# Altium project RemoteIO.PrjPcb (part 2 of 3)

## Sheet RemoteIO_IO.SchDoc
size 431 x 279 mm; Date: Not shown in title block; ApprovedBy: Not shown in title block; CheckedBy: Not shown in title block; Author: Not shown in title block; CompanyName: Not shown in title block; Engineer: Not shown in title block; Organization: Not shown in title block; Address1: Not shown in title block; Address2: Not shown in title block; Address3: Not shown in title block; Address4: Not shown in title block; DocumentNumber: 12; Revision: Use project parameter SCH_Rev; SheetNumber: 12; SheetTotal: 14; PageSetup: Record=PageOptions¦CenterHorizontal=True¦CenterVertical=True¦PrintScale=1.00¦XCorrection=1.00¦YCorrection=1.00¦PrintKind=0¦BorderSize=5000000¦LeftOffset=0¦BottomOffset=0¦Orientation=2¦PaperLength=1000¦PaperWidth=1000¦Scale=100¦PaperSource=15¦PrintQuality=600¦MediaType=1¦DitherType=10¦PaperKind=Letter¦PrintScaleMode=1
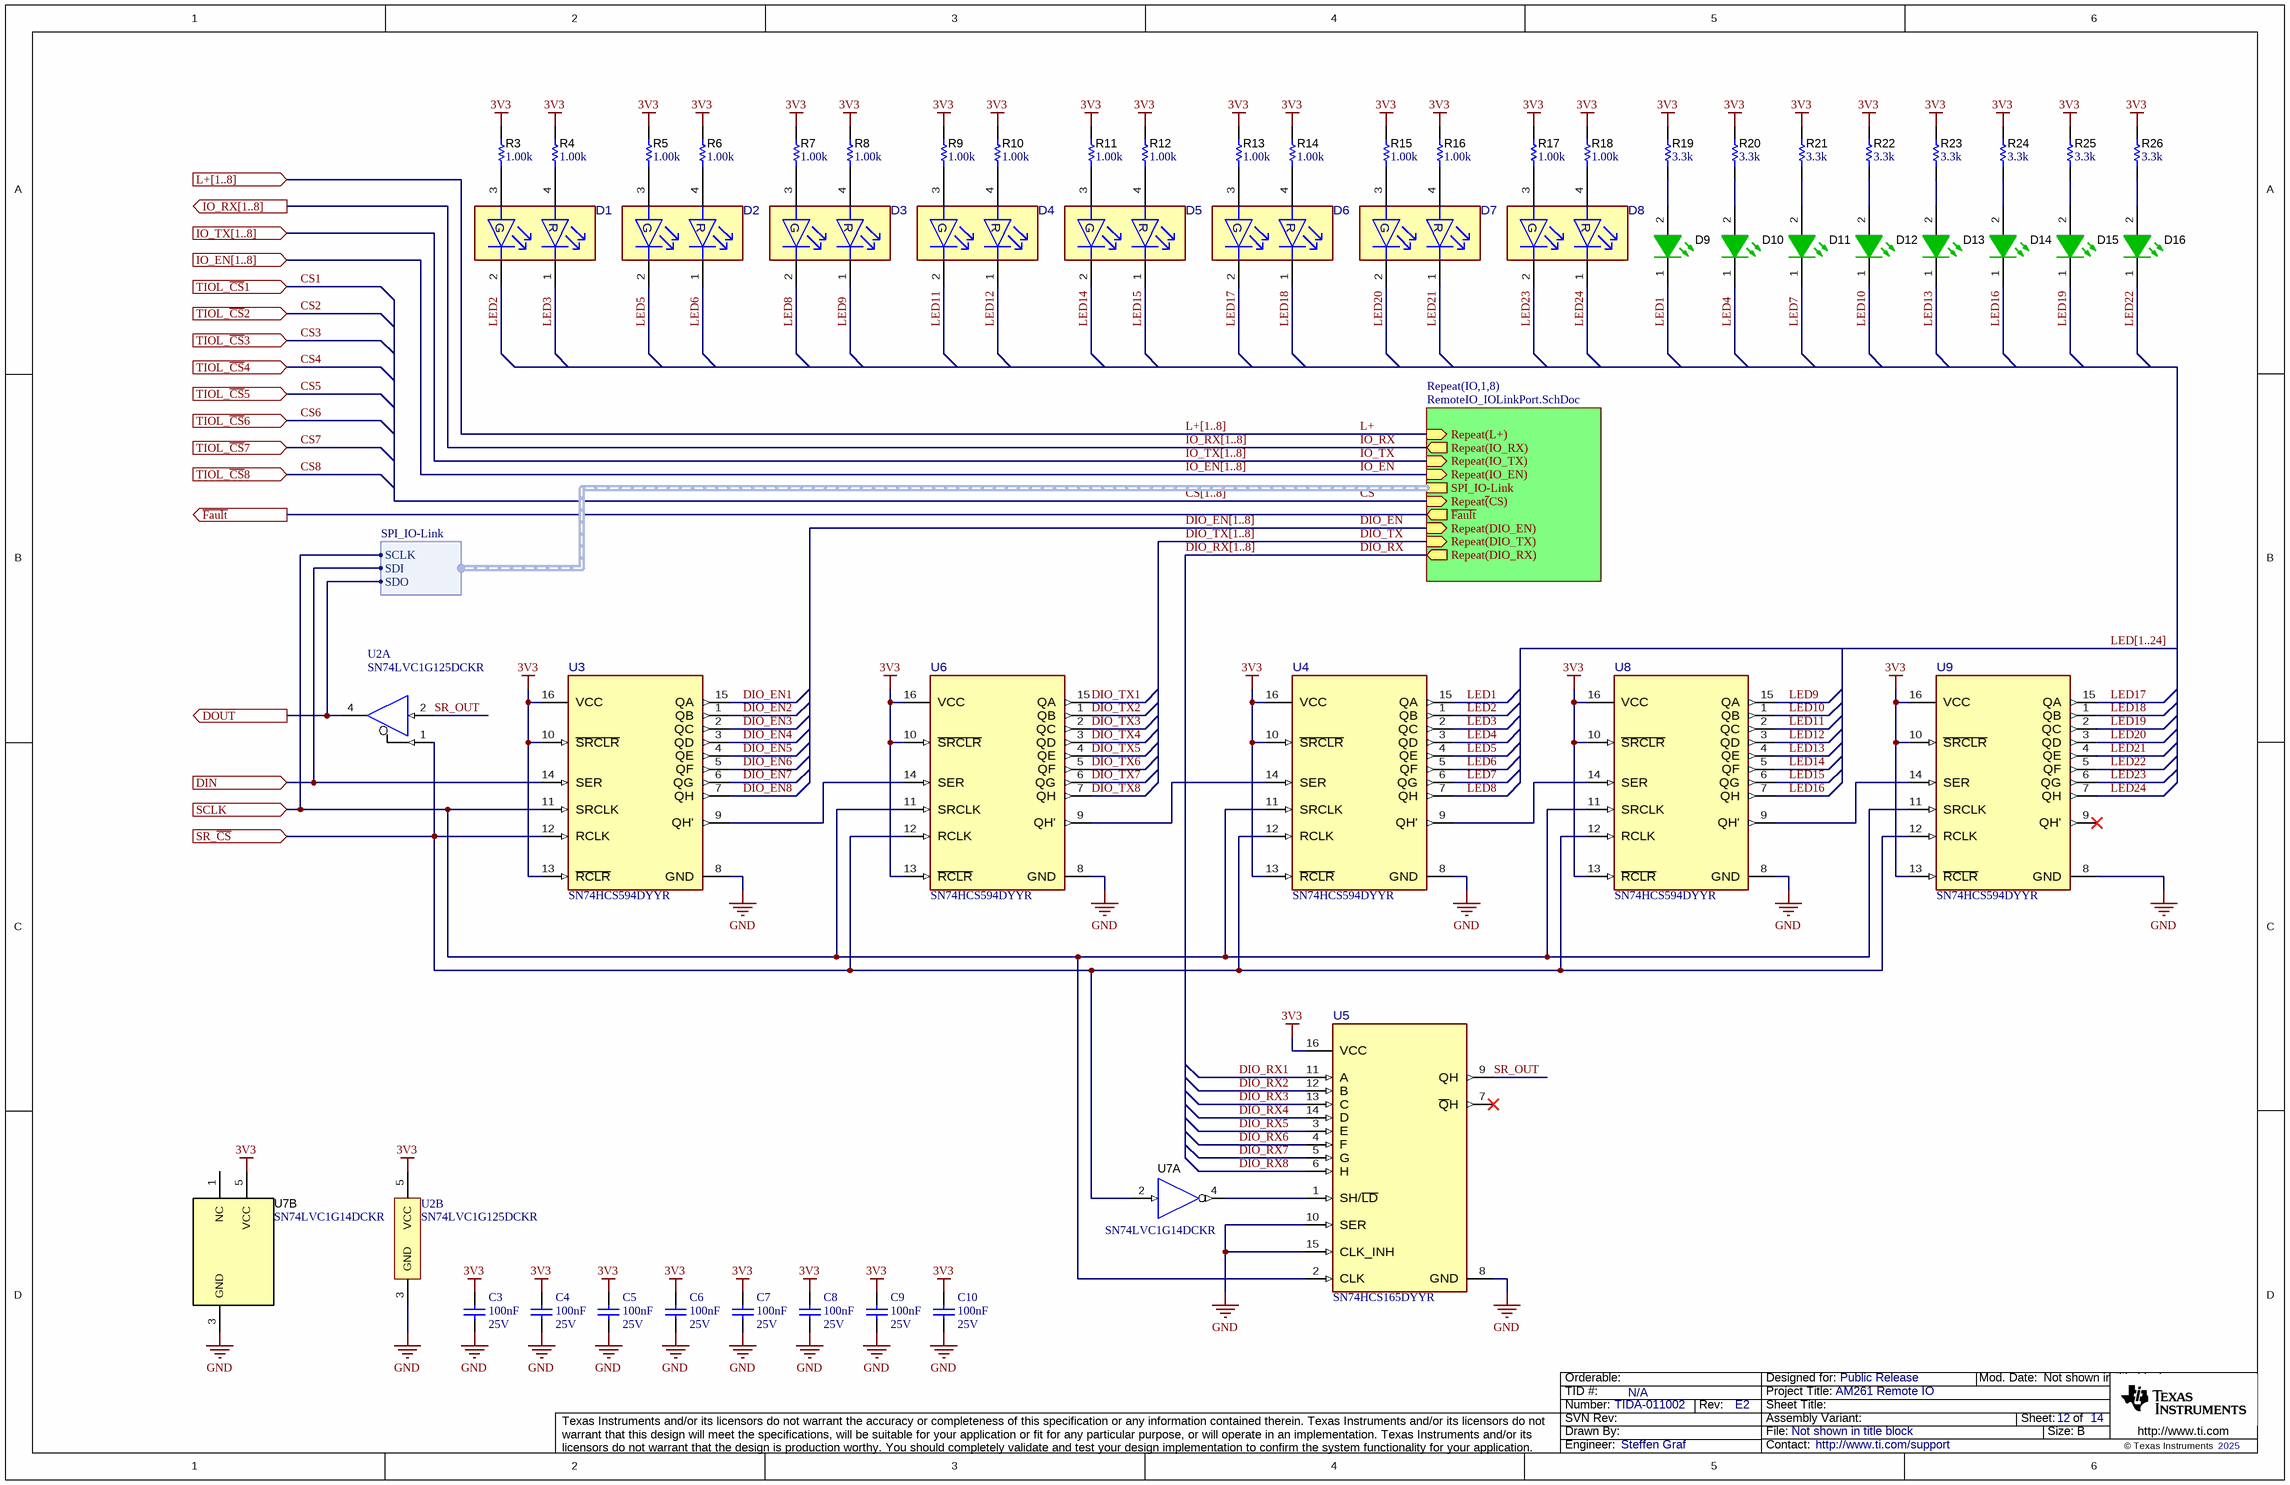
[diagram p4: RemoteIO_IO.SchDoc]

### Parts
C3  Cap_F: 100nF  Rated Voltage (DC): 25V  [WCAP-CSGP_0402_L1W0.5H0.5]  (hidden comment: 885012105018)
C4  Cap_F: 100nF  Rated Voltage (DC): 25V  [WCAP-CSGP_0402_L1W0.5H0.5]  (hidden comment: 885012105018)
C5  Cap_F: 100nF  Rated Voltage (DC): 25V  [WCAP-CSGP_0402_L1W0.5H0.5]  (hidden comment: 885012105018)
C6  Cap_F: 100nF  Rated Voltage (DC): 25V  [WCAP-CSGP_0402_L1W0.5H0.5]  (hidden comment: 885012105018)
C7  Cap_F: 100nF  Rated Voltage (DC): 25V  [WCAP-CSGP_0402_L1W0.5H0.5]  (hidden comment: 885012105018)
C8  Cap_F: 100nF  Rated Voltage (DC): 25V  [WCAP-CSGP_0402_L1W0.5H0.5]  (hidden comment: 885012105018)
C9  Cap_F: 100nF  Rated Voltage (DC): 25V  [WCAP-CSGP_0402_L1W0.5H0.5]  (hidden comment: 885012105018)
C10  Cap_F: 100nF  Rated Voltage (DC): 25V  [WCAP-CSGP_0402_L1W0.5H0.5]  (hidden comment: 885012105018)
D1  150066RG74000  [FP-150066RG74000_0606-MFG]  (value not drawn)
D2  150066RG74000  [FP-150066RG74000_0606-MFG]  (value not drawn)
D3  150066RG74000  [FP-150066RG74000_0606-MFG]  (value not drawn)
D4  150066RG74000  [FP-150066RG74000_0606-MFG]  (value not drawn)
D5  150066RG74000  [FP-150066RG74000_0606-MFG]  (value not drawn)
D6  150066RG74000  [FP-150066RG74000_0606-MFG]  (value not drawn)
D7  150066RG74000  [FP-150066RG74000_0606-MFG]  (value not drawn)
D8  150066RG74000  [FP-150066RG74000_0606-MFG]  (value not drawn)
D9  150040GS73240  [WL-SMCC_0402_Green]  (value not drawn)
D10  150040GS73240  [WL-SMCC_0402_Green]  (value not drawn)
D11  150040GS73240  [WL-SMCC_0402_Green]  (value not drawn)
D12  150040GS73240  [WL-SMCC_0402_Green]  (value not drawn)
D13  150040GS73240  [WL-SMCC_0402_Green]  (value not drawn)
D14  150040GS73240  [WL-SMCC_0402_Green]  (value not drawn)
D15  150040GS73240  [WL-SMCC_0402_Green]  (value not drawn)
D16  150040GS73240  [WL-SMCC_0402_Green]  (value not drawn)
R3  ValueDisplayed: 1.00k  [0402]  (hidden comment: CRCW04021K00FKED)
R4  ValueDisplayed: 1.00k  [0402]  (hidden comment: CRCW04021K00FKED)
R5  ValueDisplayed: 1.00k  [0402]  (hidden comment: CRCW04021K00FKED)
R6  ValueDisplayed: 1.00k  [0402]  (hidden comment: CRCW04021K00FKED)
R7  ValueDisplayed: 1.00k  [0402]  (hidden comment: CRCW04021K00FKED)
R8  ValueDisplayed: 1.00k  [0402]  (hidden comment: CRCW04021K00FKED)
R9  ValueDisplayed: 1.00k  [0402]  (hidden comment: CRCW04021K00FKED)
R10  ValueDisplayed: 1.00k  [0402]  (hidden comment: CRCW04021K00FKED)
R11  ValueDisplayed: 1.00k  [0402]  (hidden comment: CRCW04021K00FKED)
R12  ValueDisplayed: 1.00k  [0402]  (hidden comment: CRCW04021K00FKED)
R13  ValueDisplayed: 1.00k  [0402]  (hidden comment: CRCW04021K00FKED)
R14  ValueDisplayed: 1.00k  [0402]  (hidden comment: CRCW04021K00FKED)
R15  ValueDisplayed: 1.00k  [0402]  (hidden comment: CRCW04021K00FKED)
R16  ValueDisplayed: 1.00k  [0402]  (hidden comment: CRCW04021K00FKED)
R17  ValueDisplayed: 1.00k  [0402]  (hidden comment: CRCW04021K00FKED)
R18  ValueDisplayed: 1.00k  [0402]  (hidden comment: CRCW04021K00FKED)
R19  ValueDisplayed: 3.3k  [0402]  (hidden comment: CRCW04023K30JNED)
R20  ValueDisplayed: 3.3k  [0402]  (hidden comment: CRCW04023K30JNED)
R21  ValueDisplayed: 3.3k  [0402]  (hidden comment: CRCW04023K30JNED)
R22  ValueDisplayed: 3.3k  [0402]  (hidden comment: CRCW04023K30JNED)
R23  ValueDisplayed: 3.3k  [0402]  (hidden comment: CRCW04023K30JNED)
R24  ValueDisplayed: 3.3k  [0402]  (hidden comment: CRCW04023K30JNED)
R25  ValueDisplayed: 3.3k  [0402]  (hidden comment: CRCW04023K30JNED)
R26  ValueDisplayed: 3.3k  [0402]  (hidden comment: CRCW04023K30JNED)
U2  SN74LVC1G125DCKR  [DCK0005A_N]  (parts A,B of 2)
U3  SN74HCS594DYYR  [DYY0016A-MFG]
U4  SN74HCS594DYYR  [DYY0016A-MFG]
U5  SN74HCS165DYYR  [DYY0016A-MFG]
U6  SN74HCS594DYYR  [DYY0016A-MFG]
U7  SN74LVC1G14DCKR  [DCK0005A_N]  (parts A,B of 2)
U8  SN74HCS594DYYR  [DYY0016A-MFG]
U9  SN74HCS594DYYR  [DYY0016A-MFG]

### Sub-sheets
Repeat(IO,1,8) = RemoteIO_IOLinkPort.SchDoc: Repeat(L+) (in), SPI_IO-Link (harness SPI_IO-Link), Repeat(DIO_RX) (out), Repeat(DIO_EN) (in), Repeat(DIO_TX) (in), Repeat~{(}CS) (in), ~{Fault} (out), Repeat(IO_RX) (out), Repeat(IO_EN) (in), Repeat(IO_TX) (in)

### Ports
DIN (in), DOUT (out), IO_EN[1..8] (in), IO_RX[1..8] (out), IO_TX[1..8] (in), L+[1..8] (in), SCLK (in), SR_~{CS} (in), TIOL_~{CS}1 (in), TIOL_~{CS}2 (in), TIOL_~{CS}3 (in), TIOL_~{CS}4 (in), TIOL_~{CS}5 (in), TIOL_~{CS}6 (in), TIOL_~{CS}7 (in), TIOL_~{CS}8 (in), ~{Fault} (out)

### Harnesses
SPI_IO-Link: SCLK, SDI, SDO

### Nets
3V3: C3.2 C4.2 C5.2 C6.2 C7.2 C8.2 C9.2 C10.2 R3.2 R4.2 R5.2 R6.2 R7.2 R8.2 R9.2 R10.2 R11.2 R12.2 R13.2 R14.2 R15.2 R16.2 R17.2 R18.2 R19.2 R20.2 R21.2 R22.2 R23.2 R24.2 R25.2 R26.2 U2.5(VCC) U3.10(~{SRCLR}) U3.13(~{RCLR}) U3.16(VCC) U4.10(~{SRCLR}) U4.13(~{RCLR}) U4.16(VCC) U5.16(VCC) U6.10(~{SRCLR}) U6.13(~{RCLR}) U6.16(VCC) U7.5(VCC) U8.10(~{SRCLR}) U8.13(~{RCLR}) U8.16(VCC) U9.10(~{SRCLR}) U9.13(~{RCLR}) U9.16(VCC)
GND: C3.1 C4.1 C5.1 C6.1 C7.1 C8.1 C9.1 C10.1 U2.3(GND) U3.8(GND) U4.8(GND) U5.8(GND) U5.10(SER) U5.15(CLK_INH) U6.8(GND) U7.3(GND) U8.8(GND) U9.8(GND)
~{Fault}: port ~{Fault}, sheet Repeat(IO,1,8)/~{Fault}
DIN: U3.14(SER) ; port DIN, sheet Repeat(IO,1,8)/SPI_IO-Link.SDI
DIO_EN1: U3.15(QA)
DIO_EN2: U3.1(QB)
DIO_EN3: U3.2(QC)
DIO_EN4: U3.3(QD)
DIO_EN5: U3.4(QE)
DIO_EN6: U3.5(QF)
DIO_EN7: U3.6(QG)
DIO_EN8: U3.7(QH)
DIO_RX1: U5.11(A)
DIO_RX2: U5.12(B)
DIO_RX3: U5.13(C)
DIO_RX4: U5.14(D)
DIO_RX5: U5.3(E)
DIO_RX6: U5.4(F)
DIO_RX7: U5.5(G)
DIO_RX8: U5.6(H)
DIO_TX1: U6.15(QA)
DIO_TX2: U6.1(QB)
DIO_TX3: U6.2(QC)
DIO_TX4: U6.3(QD)
DIO_TX5: U6.4(QE)
DIO_TX6: U6.5(QF)
DIO_TX7: U6.6(QG)
DIO_TX8: U6.7(QH)
DOUT: U2.4(Y) ; port DOUT, sheet Repeat(IO,1,8)/SPI_IO-Link.SDO
LED1: D9.1(K) U4.15(QA)
LED2: D1.2(G_Cathode) U4.1(QB)
LED3: D1.1(R_Cathode) U4.2(QC)
LED4: D10.1(K) U4.3(QD)
LED5: D2.2(G_Cathode) U4.4(QE)
LED6: D2.1(R_Cathode) U4.5(QF)
LED7: D11.1(K) U4.6(QG)
LED8: D3.2(G_Cathode) U4.7(QH)
LED9: D3.1(R_Cathode) U8.15(QA)
LED10: D12.1(K) U8.1(QB)
LED11: D4.2(G_Cathode) U8.2(QC)
LED12: D4.1(R_Cathode) U8.3(QD)
LED13: D13.1(K) U8.4(QE)
LED14: D5.2(G_Cathode) U8.5(QF)
LED15: D5.1(R_Cathode) U8.6(QG)
LED16: D14.1(K) U8.7(QH)
LED17: D6.2(G_Cathode) U9.15(QA)
LED18: D6.1(R_Cathode) U9.1(QB)
LED19: D15.1(K) U9.2(QC)
LED20: D7.2(G_Cathode) U9.3(QD)
LED21: D7.1(R_Cathode) U9.4(QE)
LED22: D16.1(K) U9.5(QF)
LED23: D8.2(G_Cathode) U9.6(QG)
LED24: D8.1(R_Cathode) U9.7(QH)
SCLK: U3.11(SRCLK) U4.11(SRCLK) U5.2(CLK) U6.11(SRCLK) U8.11(SRCLK) U9.11(SRCLK) ; port SCLK, sheet Repeat(IO,1,8)/SPI_IO-Link.SCLK
SR_~{CS}: U2.1(~{OE}) U3.12(RCLK) U4.12(RCLK) U6.12(RCLK) U7.2(A) U8.12(RCLK) U9.12(RCLK) ; port SR_~{CS}
SR_OUT: U2.2(A) U5.9(QH)
NetD1_3: D1.3(G_Anode) R3.1
NetD1_4: D1.4(R_Anode) R4.1
NetD2_3: D2.3(G_Anode) R5.1
NetD2_4: D2.4(R_Anode) R6.1
NetD3_3: D3.3(G_Anode) R7.1
NetD3_4: D3.4(R_Anode) R8.1
NetD4_3: D4.3(G_Anode) R9.1
NetD4_4: D4.4(R_Anode) R10.1
NetD5_3: D5.3(G_Anode) R11.1
NetD5_4: D5.4(R_Anode) R12.1
NetD6_3: D6.3(G_Anode) R13.1
NetD6_4: D6.4(R_Anode) R14.1
NetD7_3: D7.3(G_Anode) R15.1
NetD7_4: D7.4(R_Anode) R16.1
NetD8_3: D8.3(G_Anode) R17.1
NetD8_4: D8.4(R_Anode) R18.1
NetD9_2: D9.2(A) R19.1
NetD10_2: D10.2(A) R20.1
NetD11_2: D11.2(A) R21.1
NetD12_2: D12.2(A) R22.1
NetD13_2: D13.2(A) R23.1
NetD14_2: D14.2(A) R24.1
NetD15_2: D15.2(A) R25.1
NetD16_2: D16.2(A) R26.1
NetU3_9: U3.9(QH') U6.14(SER)
NetU4_9: U4.9(QH') U8.14(SER)
NetU4_14: U4.14(SER) U6.9(QH')
NetU5_1: U5.1(SH/~{LD}) U7.4(Y)
NetU8_9: U8.9(QH') U9.14(SER)

Not connected (* = marked no-connect by the designer): U5 7(~{Q}H)*; U7 1(NC); U9 9(QH')*

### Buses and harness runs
bus CS[1..8]
bus DIO_EN[1..8]
bus DIO_RX[1..8]
bus DIO_TX[1..8]
bus IO_EN[1..8] = port IO_EN[1..8]
bus IO_RX[1..8] = port IO_RX[1..8]
bus IO_TX[1..8] = port IO_TX[1..8]
bus L+[1..8] = port L+[1..8]
bus LED[1..24]

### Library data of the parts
C3-C10 = CMP-0119143-1: WCAP-CSGP Multilayer Ceramic Chip Capacitor, General Purpose, size 0402, X5R, 100nF, 25VDC; Manufacturer: Wurth Elektronik; PartNumber: '885012105018; Capacitance Tolerance: +/-20%; Case/Size Code: 0402; Dissipation Factor: 10%; Insulation Resistance: 5GOhm; Technical Reference: X5R0402104M025DFCT10000
D1-D8 = CMP-0125609-1: Green, Red 520nm Green, 625nm Red LED Indication - Discrete 3.2V Green, 2V Red 0606 (1616 Metric); Manufacturer: Wurth; Angle: 130°; Color: Red, Green; LambdaD: 625/520nm; LambdaP: 630/515nm; SizeZ_mm: 0.8mm; Tjmax_C: 95°C; Vr_V: 5V; AEC Qualified: No; Forward Current: 20mA; Led Orientation: Top View; Luminous Intensity: 300/560mcd; Value: Red/Green
D9-D16 = CMP-0081765-2: LED, Green, SMD; Manufacturer: Wurth Elektronik; Vr_V: 5V; Io_A: 20mA; Tjmax_C: 95°C; Ir_A: 10µA; Power_TotalModule: 99mW; Value2: 3.2V; SizeArea_mm2: 0.5; SizeX_mm: 1; Value1: 0.099W; Angle: 120; Type: InGaN; SizeAreaWB_mm2: 3
R3-R18 = CMP-0026071-3: RES, 1.00 k, 1%, 0.063 W, AEC-Q200 Grade 0, 0402; Manufacturer: Vishay-Dale; Power_W: 63mW; TempCo: 100 ppm/C; Value_Code: 1k00; Value: 1.00k; EIA_Code: E96; Res_ohm: 1k; SizeX_mm: 1; SizeY_mm: 0.5; SizeZ_mm: 0.6; Value2: 0.063W; AEC Qualified: Y; VDC_V: 50V; AEC Category: Q200; AEC Grade: 0
R19-R26 = CMP-0026918-5: RES, 3.3 k, 5%, 0.063 W, AEC-Q200 Grade 0, 0402; Manufacturer: Vishay-Dale; Power_W: 63mW; TempCo: 200 ppm/C; Value_Code: 3k30; Value: 3.3k; EIA_Code: E24; SizeX_mm: 1; SizeY_mm: 0.5; SizeZ_mm: 0.6; Value2: 0.063W; AEC Qualified: Y; VDC_V: 50V; AEC Category: Q200; AEC Grade: 0
U2 = CMP-0051326-3: Single Bus Buffer Gate With 3-State Outputs, DCK0005A, LARGE T&R; Manufacturer: Texas Instruments; Bits(#): 1; tpd @ Nom Voltage(Max)(ns): 9,5.5,4.5,4; 3-State Output: Yes; Output Type: CMOS; Sub-Family: Non-Inverting Buffer/Driver; Logic: True; Output Drive (IOL/IOH)(Max)(mA): 32/-32; Voltage(Nom)(V): 1.8,2.5,3.3,5; ICC @ Nom Voltage(Max)(mA): 0.01; Technology Family: LVC; VCC(Min)(V): 1.65; VCC(Max)(V): 5.5; F @ Nom Voltage(Max)(Mhz): 150; Rating: Catalog; Input Type: CMOS/TTL; Schmitt Trigger: No; AEC Category: Q200; AEC Qualified: N; CompType: IC; SizeAreaWB_mm2: 9.3; SizeArea_mm2: 4.2; SizeX_mm: 2.1; SizeY_mm: 2.0; SizeZ_mm: 1.1
U3 U4 U6 U8 U9 = CMP-0093041-1: Eight-bit shift registers with Schmitt-trigger inputs and with output registers; Manufacturer: Texas Instruments; Number Of Inputs: 5; Max Supply Voltage: 6V; Min Supply Voltage: 2V; Propagation Delay: 19ns; Frequency_Fixed: 115MHz; AEC Qualified: No; Standoff Height: 0mm; TJmax_C: +150°C; TaMin_C: -40°C; PositionCount: 1; Nominal Supply Current: 0.1uA; SizeZ_mm: 1.1mm; TaMax_C: +125°C; Number Of Outputs: 8
U5 = CMP-0093040-1: Counter Shift Registers 8-bit parallel-load shift registers with Schmitt-trigger inputs; Manufacturer: Texas Instruments; TaMin_C: -40°C; SizeZ_mm: 1.1mm; PositionCount: 1; TaMax_C: +125°C; Number Of Inputs: 8; Frequency_Fixed: 170MHz; Propagation Delay: 39ns; Max Supply Voltage: 6V; Min Supply Voltage: 2V; AEC Qualified: No; TJmax_C: +150°C; Standoff Height: 0mm; Nominal Supply Current: 0.1uA
U7 = CMP-0051641-4: Single Schmitt-Trigger Inverter, DCK0005A (SOT-SC70-5); Manufacturer: Texas Instruments; Alternate PartNumber: SN74LVC1G14DCKT; Output Drive (IOL/IOH)(Max)(mA): 32/-32; Schmitt Trigger: Yes; Logic: Inverting; Bits(#): 1; Rating: Catalog; tpd @ Nom Voltage(Max)(ns): 11,6.5,5.5,5; Voltage(Nom)(V): 1.8,2.5,3.3,5; Output Type: CMOS; VCC(Min)(V): 1.65; ICC @ Nom Voltage(Max)(mA): 0.01; Input Type: CMOS/TTL; F @ Nom Voltage(Max)(Mhz): 150; VCC(Max)(V): 5.5; 3-State Output: No; AEC Category: Q200; AEC Qualified: N; CompType: IC; Green_Lifecycle: Active; Green_REACh: Passed; SizeAreaWB_mm2: 9.3; SizeArea_mm2: 4.2; SizeX_mm: 2.1; SizeY_mm: 2.0; SizeZ_mm: 1.1

## Sheet RemoteIO_IOLinkPort.SchDoc
size 431 x 279 mm; Date: Not shown in title block; ApprovedBy: Not shown in title block; CheckedBy: Not shown in title block; Author: Not shown in title block; CompanyName: Not shown in title block; Engineer: Not shown in title block; Organization: Not shown in title block; Address1: Not shown in title block; Address2: Not shown in title block; Address3: Not shown in title block; Address4: Not shown in title block; DocumentNumber: 3; Revision: Use project parameter SCH_Rev; SheetNumber: 3; SheetTotal: 14; PageSetup: Record=PageOptions¦CenterHorizontal=True¦CenterVertical=True¦PrintScale=1.00¦XCorrection=1.00¦YCorrection=1.00¦PrintKind=0¦BorderSize=5000000¦LeftOffset=0¦BottomOffset=0¦Orientation=2¦PaperLength=1000¦PaperWidth=1000¦Scale=100¦PaperSource=15¦PrintQuality=600¦MediaType=1¦DitherType=10¦PaperKind=Letter¦PrintScaleMode=1
Used 8 times, as channels IOs/IO1, IOs/IO2, IOs/IO3, IOs/IO4, IOs/IO5, IOs/IO6, IOs/IO7, IOs/IO8. Parts and nets are listed once, with the designators drawn on the sheet.
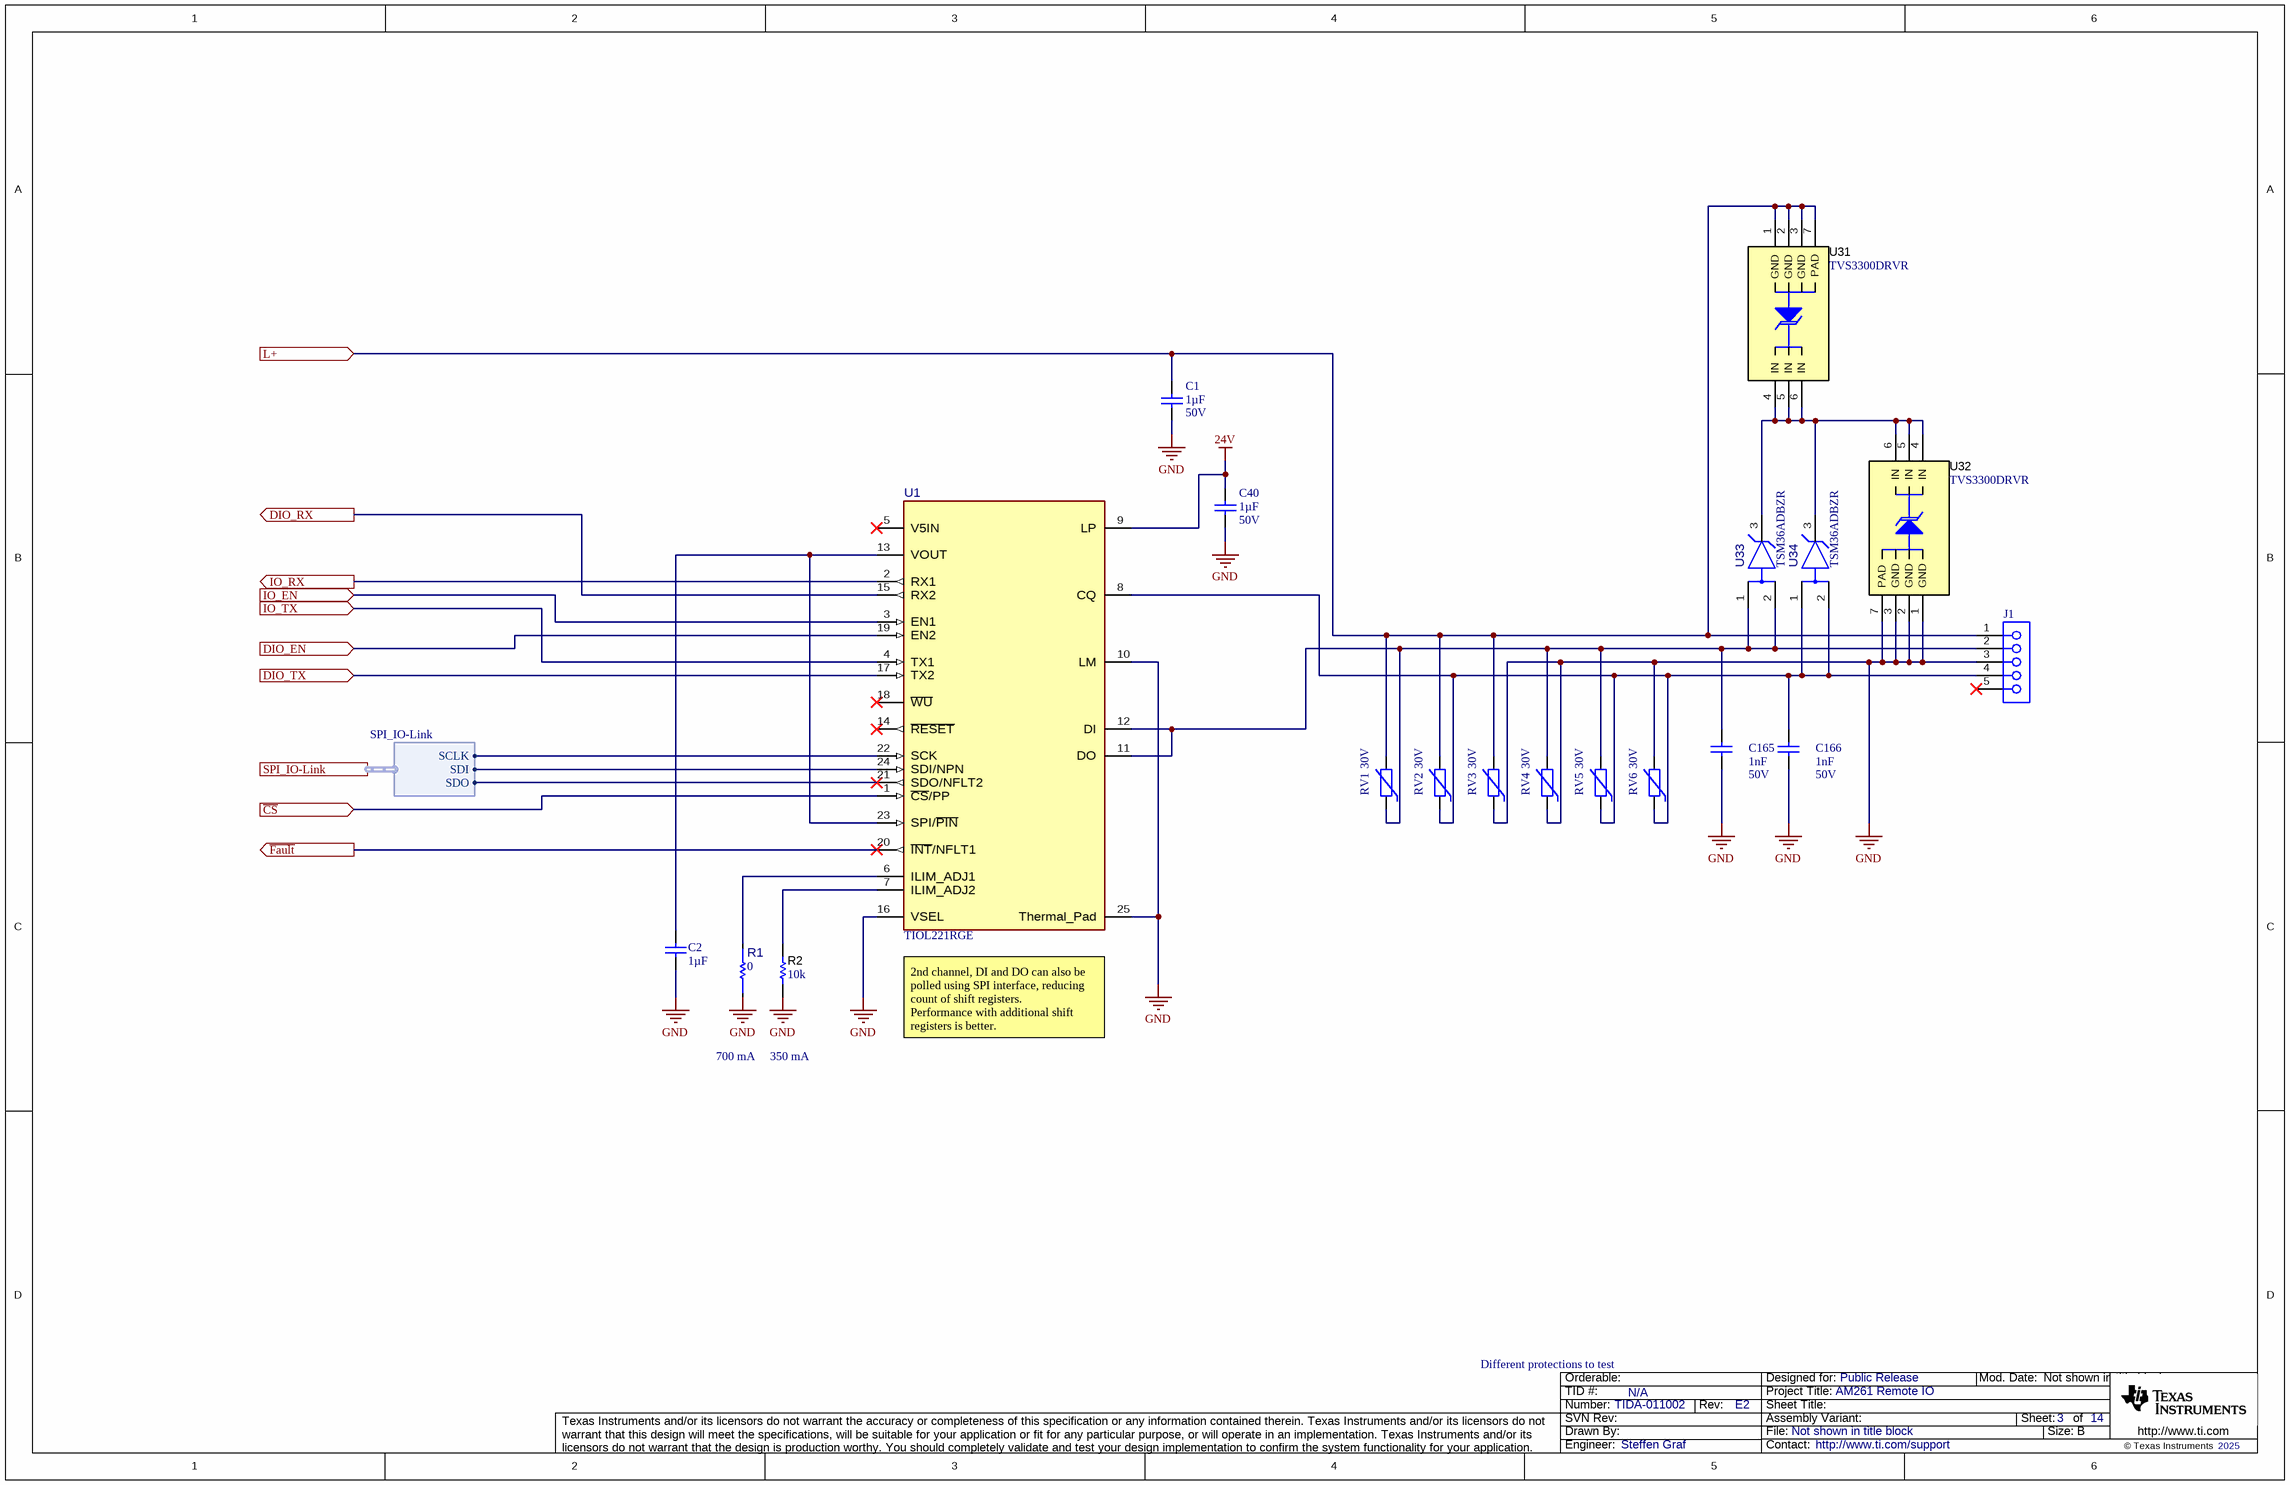
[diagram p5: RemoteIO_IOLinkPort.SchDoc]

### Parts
C1  Cap_F: 1µF  Rated Voltage (DC): 50V  [WCAP-CSGP_1206_L3.2W1.6H1.6]  (hidden comment: 885012208093)
C2  Cap_F: 1µF  [WCAP-CSGP_0603_L1.6W0.8H0.8_Reflow]  (hidden comment: 885012206052)
C40  Cap_F: 1µF  Rated Voltage (DC): 50V  [WCAP-CSGP_1206_L3.2W1.6H1.6]  (hidden comment: 885012208093)
C165  Cap_F: 1nF  Rated Voltage (DC): 50V  [WCAP-CSGP_0603_L1.6W0.8H0.8_Reflow]  (hidden comment: 885012006063)
C166  Cap_F: 1nF  Rated Voltage (DC): 50V  [WCAP-CSGP_0603_L1.6W0.8H0.8_Reflow]  (hidden comment: 885012006063)
J1  643260100605  [643260100605]  (value not drawn)
R1  value 0  [FP-CRCW04020000Z0EDC_0402-IPC_A]  (hidden comment: CRCW04020000Z0EDC)
R2  ValueDisplayed: 10k  [0402]  (hidden comment: CRCW040210K0JNED)
RV1  Operating Voltage (AC): 30V  [WE-VS_0603]  (hidden comment: 30VAC, 38VDC)
RV2  Operating Voltage (AC): 30V  [WE-VS_0603]  (hidden comment: 30VAC, 38VDC)
RV3  Operating Voltage (AC): 30V  [WE-VS_0603]  (hidden comment: 30VAC, 38VDC)
RV4  Operating Voltage (AC): 30V  [WE-VS_0603]  (hidden comment: 30VAC, 38VDC)
RV5  Operating Voltage (AC): 30V  [WE-VS_0603]  (hidden comment: 30VAC, 38VDC)
RV6  Operating Voltage (AC): 30V  [WE-VS_0603]  (hidden comment: 30VAC, 38VDC)
U1  TIOL221RGE  [RGE0024H-MFG]
U31  TVS3300DRVR  [DRV0006A]
U32  TVS3300DRVR  [DRV0006A]
U33  TSM36ADBZR  [DBZ0003A-MFG]
U34  TSM36ADBZR  [DBZ0003A-MFG]

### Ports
DIO_EN (in), DIO_RX (out), DIO_TX (in), IO_EN (in), IO_RX (out), IO_TX (in), L+ (in), SPI_IO-Link (harness SPI_IO-Link), ~{CS} (in), ~{Fault} (out)

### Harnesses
SPI_IO-Link: SCLK, SDI, SDO

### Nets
24V: C40.2 U1.9(LP)
GND: C1.1 C2.1 C40.1 C165.1 C166.1 J1.3 R1.1 R2.1 RV3.1 RV4.1 RV6.2 U1.10(LM) U1.16(VSEL) U1.25(Thermal_Pad) U32.1(GND) U32.2(GND) U32.3(GND) U32.7(PAD)
~{CS}: U1.1(~{CS}/PP) ; port ~{CS}
~{Fault}: U1.20(~{INT}/NFLT1) ; port ~{Fault}
DIO_EN: U1.19(EN2) ; port DIO_EN
DIO_RX: U1.15(RX2) ; port DIO_RX
DIO_TX: U1.17(TX2) ; port DIO_TX
IO_EN: U1.3(EN1) ; port IO_EN
IO_RX: U1.2(RX1) ; port IO_RX
IO_TX: U1.4(TX1) ; port IO_TX
L+: C1.2 J1.1 RV1.2 RV2.2 RV3.2 U31.1(GND) U31.2(GND) U31.3(GND) U31.7(PAD) ; port L+
NetC2_2: C2.2 U1.13(VOUT) U1.23(SPI/~{PIN})
NetC165_2: C165.2 J1.2 RV1.1 RV4.2 RV5.2 U1.11(DO) U1.12(DI) U33.1(GND) U33.2(GND)
NetC166_2: C166.2 J1.4 RV2.1 RV5.1 RV6.1 U1.8(CQ) U34.1(GND) U34.2(GND)
NetR1_2: R1.2 U1.6(ILIM_ADJ1)
NetR2_2: R2.2 U1.7(ILIM_ADJ2)
NetU1_21: U1.21(SDO/NFLT2) ; port SPI_IO-Link.SDO
NetU1_22: U1.22(SCK) ; port SPI_IO-Link.SCLK
NetU1_24: U1.24(SDI/NPN) ; port SPI_IO-Link.SDI
NetU31_4: U31.4(IN) U31.5(IN) U31.6(IN) U32.4(IN) U32.5(IN) U32.6(IN) U33.3(IO) U34.3(IO)

Not connected (* = marked no-connect by the designer): J1 5*; U1 5(V5IN)* 14(~{RESET})* 18(~{WU})*

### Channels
IOs/IO1: designators end in .1; ports DIO_EN=DIO_EN1 DIO_RX=DIO_RX1 DIO_TX=DIO_TX1 IO_EN=IO_EN1 IO_RX=IO_RX1 IO_TX=IO_TX1 L+=L+1 ~{CS}=CS1 ~{Fault}=~{Fault}
IOs/IO2: designators end in .2; ports DIO_EN=DIO_EN2 DIO_RX=DIO_RX2 DIO_TX=DIO_TX2 IO_EN=IO_EN2 IO_RX=IO_RX2 IO_TX=IO_TX2 L+=L+2 ~{CS}=CS2 ~{Fault}=~{Fault}
IOs/IO3: designators end in .3; ports DIO_EN=DIO_EN3 DIO_RX=DIO_RX3 DIO_TX=DIO_TX3 IO_EN=IO_EN3 IO_RX=IO_RX3 IO_TX=IO_TX3 L+=L+3 ~{CS}=CS3 ~{Fault}=~{Fault}
IOs/IO4: designators end in .4; ports DIO_EN=DIO_EN4 DIO_RX=DIO_RX4 DIO_TX=DIO_TX4 IO_EN=IO_EN4 IO_RX=IO_RX4 IO_TX=IO_TX4 L+=L+4 ~{CS}=CS4 ~{Fault}=~{Fault}
IOs/IO5: designators end in .5; ports DIO_EN=DIO_EN5 DIO_RX=DIO_RX5 DIO_TX=DIO_TX5 IO_EN=IO_EN5 IO_RX=IO_RX5 IO_TX=IO_TX5 L+=L+5 ~{CS}=CS5 ~{Fault}=~{Fault}
IOs/IO6: designators end in .6; ports DIO_EN=DIO_EN6 DIO_RX=DIO_RX6 DIO_TX=DIO_TX6 IO_EN=IO_EN6 IO_RX=IO_RX6 IO_TX=IO_TX6 L+=L+6 ~{CS}=CS6 ~{Fault}=~{Fault}
IOs/IO7: designators end in .7; ports DIO_EN=DIO_EN7 DIO_RX=DIO_RX7 DIO_TX=DIO_TX7 IO_EN=IO_EN7 IO_RX=IO_RX7 IO_TX=IO_TX7 L+=L+7 ~{CS}=CS7 ~{Fault}=~{Fault}
IOs/IO8: designators end in .8; ports DIO_EN=DIO_EN8 DIO_RX=DIO_RX8 DIO_TX=DIO_TX8 IO_EN=IO_EN8 IO_RX=IO_RX8 IO_TX=IO_TX8 L+=L+8 ~{CS}=CS8 ~{Fault}=~{Fault}

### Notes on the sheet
- (near U1) 2nd channel, DI and DO can also be polled using SPI interface, reducing count of shift registers.
  Performance with additional shift registers is better.
- 700 mA
- 350 mA
- Different protections to test

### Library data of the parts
C1 C40 = CMP-0119636-1: WCAP-CSGP Multilayer Ceramic Chip Capacitor, General Purpose, size 1206, X7R, 1µF, 50VDC; Manufacturer: Wurth Elektronik; PartNumber: '885012208093; Capacitance Tolerance: +/-10%; Case/Size Code: 1206; Dissipation Factor: 3%; Insulation Resistance: 0.5GOhm; Technical Reference: X7R1206105K050DFCT10000
C2 = CMP-0115435-1: WCAP-CSGP Multilayer Ceramic Chip Capacitor, General Purpose, size 0603, X7R, 1µF, 16VDC; Manufacturer: Wurth Elektronik; Capacitance Tolerance: +/-10%; Case/Size Code: 0603; Dissipation Factor: 10%; Insulation Resistance: 0.1GOhm; Rated Voltage (DC): 16V; Technical Reference: X7R0603105K016DFCT10000
C165 C166 = CMP-0118895-1: WCAP-CSGP Multilayer Ceramic Chip Capacitor, General Purpose, size 0603, NP0, 1nF, 50VDC; Manufacturer: Wurth Elektronik; Capacitance Tolerance: +/-5%; Case/Size Code: 0603; Insulation Resistance: 10GOhm; Q Factor: 1000; Technical Reference: NP00603102J050DFCT10000
J1 = 643260100605: WR-CIRCM12 Screw Mating Panel Connector Female Metal PG9, THT, 5p; Manufacturer: Wurth Elektronik; PartNumber: '643260100605; Insulation Resistance: 100MΩ; Polarity: 5; Rated Current: 5A; Working Voltage: 60V; Withstanding Voltage: 1000V AC
R1 = CMP-0093210-1: Jumper 0.063W, 1/16W Chip Resistor 0402 (1005 Metric) - Thick Film; Manufacturer: Vishay; AEC Qualified: No; VDC_V: 50V; Power_W: 63mW; SizeZ_mm: 0.35mm
R2 = CMP-0026825-5: RES, 10 k, 5%, 0.063 W, AEC-Q200 Grade 0, 0402; Manufacturer: Vishay-Dale; Power_W: 63mW; TempCo: 200 ppm/C; Value_Code: 10k0; Value: 10k; EIA_Code: E24; SizeX_mm: 1; SizeY_mm: 0.5; SizeZ_mm: 0.6; Value2: 0.063W; AEC Qualified: Y; VDC_V: 50V; AEC Category: Q200; AEC Grade: 0
RV1-RV6 = 82556300: WE-VS SMT Varistor, size 0603, 30VAC, 38VDC; Manufacturer: Wurth Elektronik; Case/Size Code: 0603; Clamping Voltage: 77V; Energy Absorption: 0.1J; Operating Voltage (DC): 38V; (Reverse) Breakdown Voltage: 47V; (Reverse) Peak Pulse Current: 30A; Value: 30V
U1 = CMP-0044977-1: Dual Channel IO-Link Device PHY with Integrated LDO and SPI Interface; Manufacturer: Texas Instruments; SizeZ_mm: 1mm; AEC Qualified: No; Interface: SPI,Other; Max Supply Voltage: 36V; Min Supply Voltage: 4.5V; Standoff Height: 0mm; TaMax_C: +125°C; TaMin_C: -40°C; TJmax_C: +150°C
U31 U32 = CMP-0013424-7: 33-V Precision Surge Protection Clamp, DRV0006A (WSON-6); Manufacturer: Texas Instruments; Alternate PartNumber: TVS3300DRVT; SizeX_mm: 2; CompType: IC; SizeZ_mm: 0.8; SizeArea_mm2: 4; SizeAreaWB_mm2: 9; U/M: EA
U33 U34 = CMP-0097428-1: Surge Protection Device in SOT-23 Package; Manufacturer: Texas Instruments; Breakdown Voltage: 37.8V; TJmax_C: +150°C; Number Of Channels: 1; Direction: Unidirectional; Standoff Height: 0.01mm; Cap_F: 50pF; VRWM: 36V; Ipp: 41A; Ppk: 2000W; SizeZ_mm: 1.12mm; TaMin_C: -55°C; AEC Qualified: No; Clamping Voltage: 57V

## Sheet RemoteIO_Hardware.SchDoc
size 431 x 279 mm; Date: Not shown in title block; ApprovedBy: Not shown in title block; CheckedBy: Not shown in title block; Author: Not shown in title block; CompanyName: Not shown in title block; Engineer: Not shown in title block; Organization: Not shown in title block; Address1: Not shown in title block; Address2: Not shown in title block; Address3: Not shown in title block; Address4: Not shown in title block; DocumentNumber: 14; Revision: Use project parameter SCH_Rev; SheetNumber: 14; SheetTotal: 14; PageSetup: Record=PageOptions¦CenterHorizontal=True¦CenterVertical=True¦PrintScale=1.00¦XCorrection=1.00¦YCorrection=1.00¦PrintKind=0¦BorderSize=5000000¦LeftOffset=0¦BottomOffset=0¦Orientation=2¦PaperLength=1000¦PaperWidth=1000¦Scale=100¦PaperSource=15¦PrintQuality=600¦MediaType=1¦DitherType=10¦PaperKind=Letter¦PrintScaleMode=1
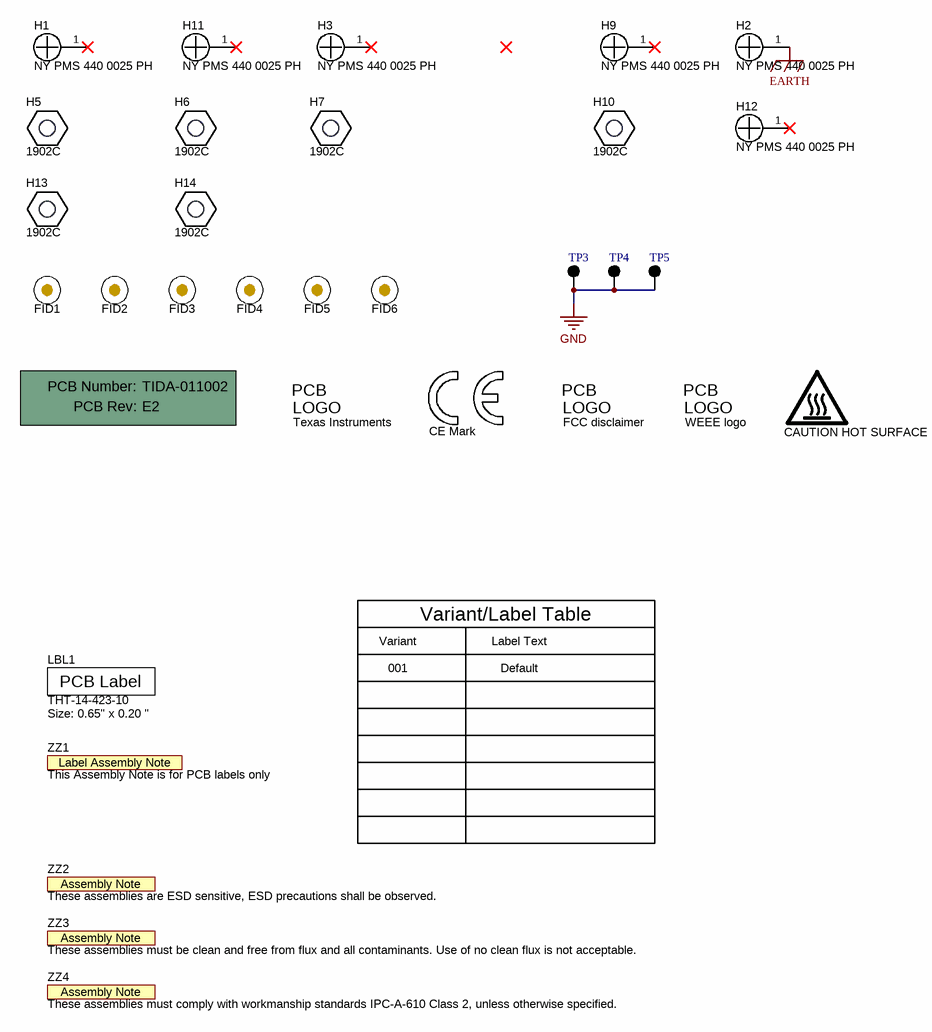
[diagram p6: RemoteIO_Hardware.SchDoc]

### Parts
!PCB  Printed Circuit Board  (value not drawn)  (mechanical)
FID1  Fiducial  [Fiducial10-20]  (value not drawn)
FID2  Fiducial  [Fiducial10-20]  (value not drawn)
FID3  Fiducial  [Fiducial10-20]  (value not drawn)
FID4  Fiducial  [Fiducial10-20]  (value not drawn)
FID5  Fiducial  [Fiducial10-20]  (value not drawn)
FID6  Fiducial  [Fiducial10-20]  (value not drawn)
H1  NY PMS 440 0025 PH  [NY PMS 440 0025 PH]
H2  NY PMS 440 0025 PH  [NY PMS 440 0025 PH]
H3  NY PMS 440 0025 PH  [NY PMS 440 0025 PH]
H5  1902C  [Keystone_1902C]
H6  1902C  [Keystone_1902C]
H7  1902C  [Keystone_1902C]
H9  NY PMS 440 0025 PH  [NY PMS 440 0025 PH]
H10  1902C  [Keystone_1902C]
H11  NY PMS 440 0025 PH  [NY PMS 440 0025 PH]
H12  NY PMS 440 0025 PH  [NY PMS 440 0025 PH]
H13  1902C  [Keystone_1902C]
H14  1902C  [Keystone_1902C]
LBL1  THT-14-423-10  Note: Size: 0.65" x 0.20 "  [Label_650x200]
Logo1  Texas Instruments  [TI_Stacked_Overlay_Small]  (no BOM)
Logo2  CE Mark  [CE_Mark_5mm]  (no BOM)
Logo3  FCC disclaimer  [FCC_disclaimer]  (no BOM)
Logo4  WEEE logo  [WEEE_Minimum]  (no BOM)
Logo5  CAUTION HOT SURFACE  [IEC_HotSurface_Small]  (no BOM)
TP3  5006  [Keystone5006]  (value not drawn)
TP4  5006  [Keystone5006]  (value not drawn)
TP5  5006  [Keystone5006]  (value not drawn)
ZZ1  This Assembly Note is for PCB labels only  [AssemblyNoteLabel]  (no BOM)
ZZ2  These assemblies are ESD sensitive, ESD precautions shall be observed.  [AssemblyNote]  (no BOM)
ZZ3  These assemblies must be clean and free from flux and all contaminants. Use of no clean flux is not acceptable.  [AssemblyNote]  (no BOM)
ZZ4  These assemblies must comply with workmanship standards IPC-A-610 Class 2, unless otherwise specified.  [AssemblyNote]  (no BOM)

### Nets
EARTH: H2.1
GND: TP3.1 TP4.1 TP5.1

Not connected (* = marked no-connect by the designer): H1 1*; H3 1*; H9 1*; H11 1*; H12 1*

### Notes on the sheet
- Variant
- Variant/Label Table
- Label Text
- 001
- Default

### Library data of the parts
!PCB = CMP-0003618-2: Manufacturer: Any; PartNumber: TIDA-011002
FID1-FID6 = CMP-0077181-1: Fiducial mark.  There is nothing to buy or mount.
H1-H3 H9 H11 H12 = CMP-0003617-1: Machine Screw, Round, #4-40 x 1/4, Nylon, Philips panhead; Manufacturer: B&F Fastener Supply; CompType: Hardware
H5-H7 H10 H13 H14 = CMP-0003610-1: Standoff, Hex, 0.5"L #4-40 Nylon; Manufacturer: Keystone; CompType: Hardware
LBL1 = CMP-0003625-1: Thermal Transfer Printable Labels, 0.650" W x 0.200" H - 10,000 per roll; Manufacturer: Brady; CompType: Label
Logo1 = CMP-0074838-1: Texas Instrument Corporate Signature; SymbolCreator: a0412235; Lib Reference: TI_Logo; Library Reference: Logo
Logo2 = CMP-0074844-1: SymbolCreator: a0412235
Logo3 = CMP-0074847-1: FCC_disclaimer; Library Reference: Logo
Logo4 = CMP-0074769-1
Logo5 = CMP-0074837-2: IEC 61010-1 Hot Surface Warning; Manufacturer: Texas Instruments; CompType: IC; AEC Category: Q200; SymbolCreator: a0412235
TP3-TP5 = CMP-0055143-2: Test Point, Compact, Black, TH; Manufacturer: Keystone Electronics; ContactFinish: Silver; Green_Lifecycle: Active; Green_REACh: Passed; CT: TRUE; CNHeader: FALSE
ZZ1 = CMP-0003616-3
ZZ2 = CMP-0077236-1
ZZ3 = CMP-0077237-1
ZZ4 = CMP-0077238-1

## Sheet RemoteIO_HSS.SchDoc
size 431 x 279 mm; Date: Not shown in title block; ApprovedBy: Not shown in title block; CheckedBy: Not shown in title block; Author: Not shown in title block; CompanyName: Not shown in title block; Engineer: Not shown in title block; Organization: Not shown in title block; Address1: Not shown in title block; Address2: Not shown in title block; Address3: Not shown in title block; Address4: Not shown in title block; DocumentNumber: 4; Revision: Use project parameter SCH_Rev; SheetNumber: 4; SheetTotal: 14; PageSetup: Record=PageOptions¦CenterHorizontal=True¦CenterVertical=True¦PrintScale=1.00¦XCorrection=1.00¦YCorrection=1.00¦PrintKind=0¦BorderSize=5000000¦LeftOffset=0¦BottomOffset=0¦Orientation=2¦PaperLength=1000¦PaperWidth=1000¦Scale=100¦PaperSource=15¦PrintQuality=600¦MediaType=1¦DitherType=10¦PaperKind=Letter¦PrintScaleMode=1
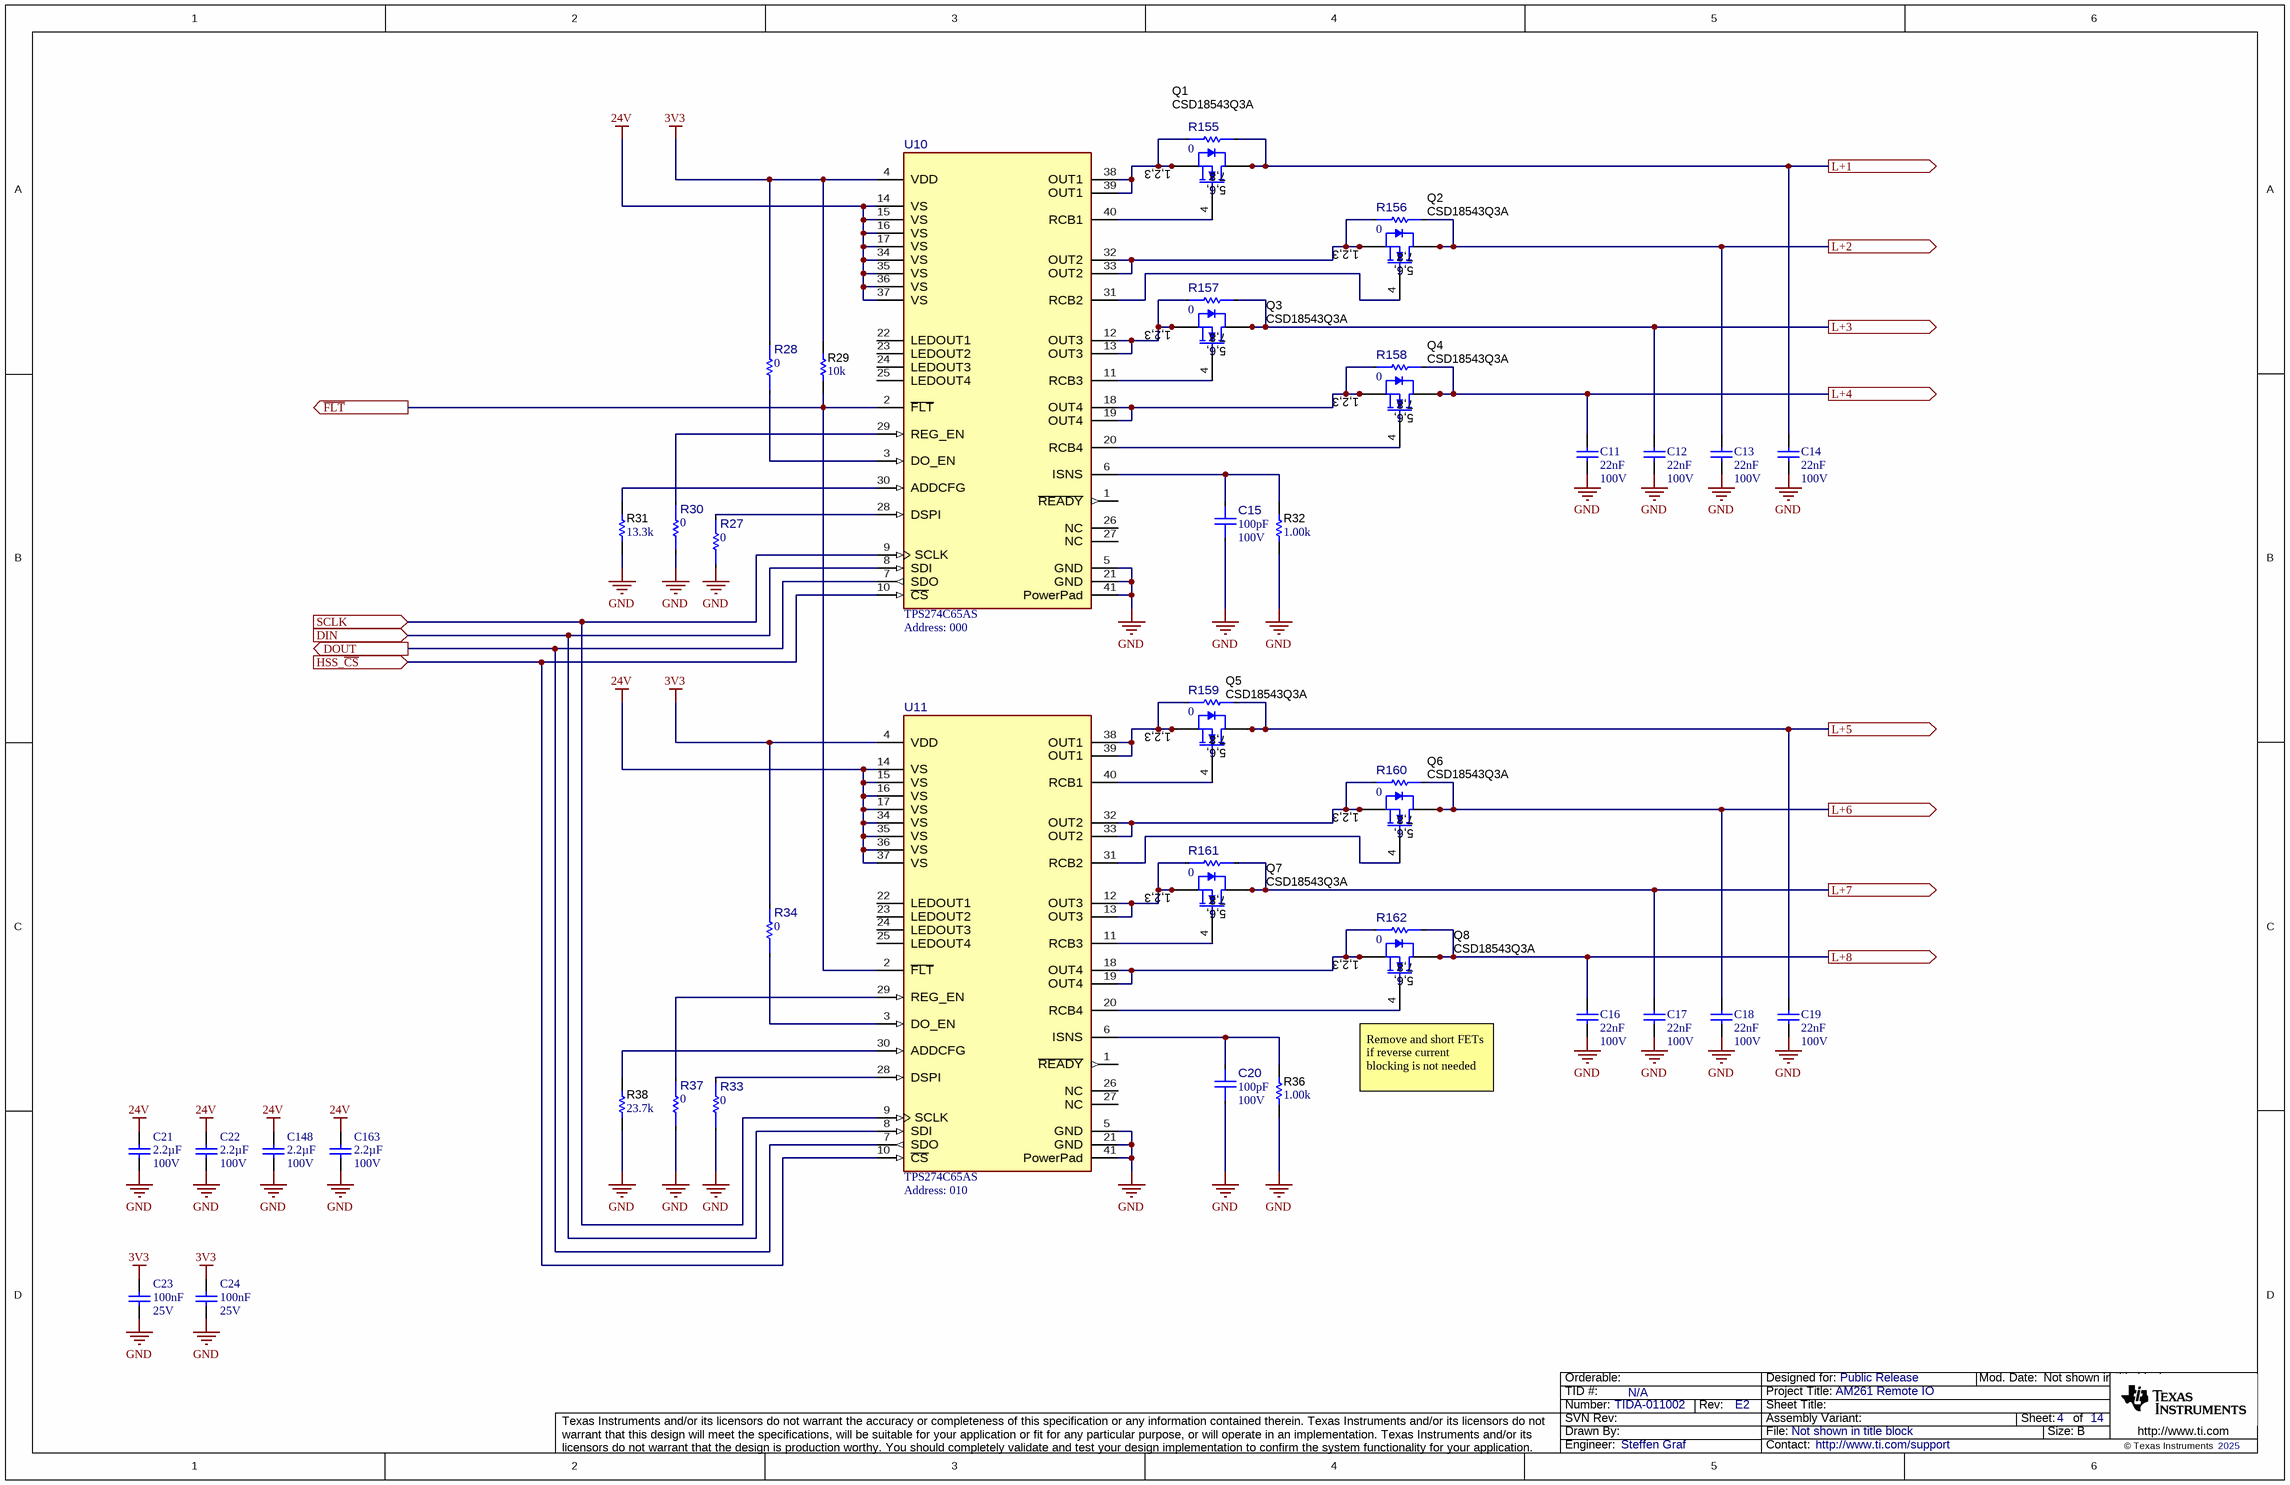
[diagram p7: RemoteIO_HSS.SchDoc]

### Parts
C11  Cap_F: 22nF  Rated Voltage (DC): 100V  [WCAP-CSGP_0805_L2W1.25H0.8_Reflow]  (hidden comment: 885012207124)
C12  Cap_F: 22nF  Rated Voltage (DC): 100V  [WCAP-CSGP_0805_L2W1.25H0.8_Reflow]  (hidden comment: 885012207124)
C13  Cap_F: 22nF  Rated Voltage (DC): 100V  [WCAP-CSGP_0805_L2W1.25H0.8_Reflow]  (hidden comment: 885012207124)
C14  Cap_F: 22nF  Rated Voltage (DC): 100V  [WCAP-CSGP_0805_L2W1.25H0.8_Reflow]  (hidden comment: 885012207124)
C15  ValueDisplayed: 100pF  VDC_V: 100V  [FP-885012005080_0402-MFG]  (hidden comment: 885012005080)
C16  Cap_F: 22nF  Rated Voltage (DC): 100V  [WCAP-CSGP_0805_L2W1.25H0.8_Reflow]  (hidden comment: 885012207124)
C17  Cap_F: 22nF  Rated Voltage (DC): 100V  [WCAP-CSGP_0805_L2W1.25H0.8_Reflow]  (hidden comment: 885012207124)
C18  Cap_F: 22nF  Rated Voltage (DC): 100V  [WCAP-CSGP_0805_L2W1.25H0.8_Reflow]  (hidden comment: 885012207124)
C19  Cap_F: 22nF  Rated Voltage (DC): 100V  [WCAP-CSGP_0805_L2W1.25H0.8_Reflow]  (hidden comment: 885012207124)
C20  ValueDisplayed: 100pF  VDC_V: 100V  [FP-885012005080_0402-MFG]  (hidden comment: 885012005080)
C21  Cap_F: 2.2µF  Rated Voltage (DC): 100V  [WCAP-CSGP_1210_L3.2W2.5H2.5]  (hidden comment: 885012209071)
C22  Cap_F: 2.2µF  Rated Voltage (DC): 100V  [WCAP-CSGP_1210_L3.2W2.5H2.5]  (hidden comment: 885012209071)
C23  Cap_F: 100nF  Rated Voltage (DC): 25V  [WCAP-CSGP_0402_L1W0.5H0.5]  (hidden comment: 885012105018)
C24  Cap_F: 100nF  Rated Voltage (DC): 25V  [WCAP-CSGP_0402_L1W0.5H0.5]  (hidden comment: 885012105018)
C148  Cap_F: 2.2µF  Rated Voltage (DC): 100V  [WCAP-CSGP_1210_L3.2W2.5H2.5]  (hidden comment: 885012209071)
C163  Cap_F: 2.2µF  Rated Voltage (DC): 100V  [WCAP-CSGP_1210_L3.2W2.5H2.5]  (hidden comment: 885012209071)
Q1  CSD18543Q3A  [DNH0008A]
Q2  CSD18543Q3A  [DNH0008A]
Q3  CSD18543Q3A  [DNH0008A]
Q4  CSD18543Q3A  [DNH0008A]
Q5  CSD18543Q3A  [DNH0008A]
Q6  CSD18543Q3A  [DNH0008A]
Q7  CSD18543Q3A  [DNH0008A]
Q8  CSD18543Q3A  [DNH0008A]
R27  value 0  [FP-CRCW04020000Z0EDC_0402-MFG]  (hidden comment: CRCW04020000Z0EDC)
R28  value 0  [FP-CRCW04020000Z0EDC_0402-MFG]  (hidden comment: CRCW04020000Z0EDC)
R29  ValueDisplayed: 10k  [0402]  (hidden comment: CRCW040210K0JNED)
R30  value 0  [FP-CRCW04020000Z0EDC_0402-MFG]  (hidden comment: CRCW04020000Z0EDC)
R31  ValueDisplayed: 13.3k  [0402]  (hidden comment: CRCW040213K3FKED)
R32  ValueDisplayed: 1.00k  [0402]  (hidden comment: CRCW04021K00FKED)
R33  value 0  [FP-CRCW04020000Z0EDC_0402-MFG]  (hidden comment: CRCW04020000Z0EDC)
R34  value 0  [FP-CRCW04020000Z0EDC_0402-MFG]  (hidden comment: CRCW04020000Z0EDC)
R36  ValueDisplayed: 1.00k  [0402]  (hidden comment: CRCW04021K00FKED)
R37  value 0  [FP-CRCW04020000Z0EDC_0402-MFG]  (hidden comment: CRCW04020000Z0EDC)
R38  ValueDisplayed: 23.7k  [0402]  (hidden comment: CRCW040223K7FKED)
R155  value 0  [FP-CRCW04020000Z0EDC_0402-MFG]  (hidden comment: CRCW04020000Z0EDC)
R156  value 0  [FP-CRCW04020000Z0EDC_0402-MFG]  (hidden comment: CRCW04020000Z0EDC)
R157  value 0  [FP-CRCW04020000Z0EDC_0402-MFG]  (hidden comment: CRCW04020000Z0EDC)
R158  value 0  [FP-CRCW04020000Z0EDC_0402-MFG]  (hidden comment: CRCW04020000Z0EDC)
R159  value 0  [FP-CRCW04020000Z0EDC_0402-MFG]  (hidden comment: CRCW04020000Z0EDC)
R160  value 0  [FP-CRCW04020000Z0EDC_0402-MFG]  (hidden comment: CRCW04020000Z0EDC)
R161  value 0  [FP-CRCW04020000Z0EDC_0402-MFG]  (hidden comment: CRCW04020000Z0EDC)
R162  value 0  [FP-CRCW04020000Z0EDC_0402-MFG]  (hidden comment: CRCW04020000Z0EDC)
U10  TPS274C65AS  [RHA0040M-MFG]
U11  TPS274C65AS  [RHA0040M-MFG]

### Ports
DIN (in), DOUT (out), HSS_~{CS} (in), L+1 (out), L+2 (out), L+3 (out), L+4 (out), L+5 (out), L+6 (out), L+7 (out), L+8 (out), SCLK (in), ~{FLT} (out)

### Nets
3V3: C23.2 C24.2 R28.2 R29.2 R34.2 U10.4(VDD) U11.4(VDD)
24V: C21.2 C22.2 C148.2 C163.2 U10.14(VS) U10.15(VS) U10.16(VS) U10.17(VS) U10.34(VS) U10.35(VS) U10.36(VS) U10.37(VS) U11.14(VS) U11.15(VS) U11.16(VS) U11.17(VS) U11.34(VS) U11.35(VS) U11.36(VS) U11.37(VS)
GND: C11.1 C12.1 C13.1 C14.1 C15.1 C16.1 C17.1 C18.1 C19.1 C20.1 C21.1 C22.1 C23.1 C24.1 C148.1 C163.1 R27.1 R30.2 R31.1 R32.1 R33.1 R36.1 R37.2 R38.1 U10.5(GND) U10.21(GND) U10.41(PowerPad) U11.5(GND) U11.21(GND) U11.41(PowerPad)
~{FLT}: R29.1 U10.2(~{FLT}) U11.2(~{FLT}) ; port ~{FLT}
DIN: U10.8(SDI) U11.8(SDI) ; port DIN
DOUT: U10.7(SDO) U11.7(SDO) ; port DOUT
HSS_~{CS}: U10.10(~{CS}) U11.10(~{CS}) ; port HSS_~{CS}
L+1: C14.2 Q1.5(D) Q1.6(D) Q1.7(D) Q1.8(D) Q1.9(D) R155.2 ; port L+1
L+2: C13.2 Q2.5(D) Q2.6(D) Q2.7(D) Q2.8(D) Q2.9(D) R156.2 ; port L+2
L+3: C12.2 Q3.5(D) Q3.6(D) Q3.7(D) Q3.8(D) Q3.9(D) R157.2 ; port L+3
L+4: C11.2 Q4.5(D) Q4.6(D) Q4.7(D) Q4.8(D) Q4.9(D) R158.2 ; port L+4
L+5: C19.2 Q5.5(D) Q5.6(D) Q5.7(D) Q5.8(D) Q5.9(D) R159.2 ; port L+5
L+6: C18.2 Q6.5(D) Q6.6(D) Q6.7(D) Q6.8(D) Q6.9(D) R160.2 ; port L+6
L+7: C17.2 Q7.5(D) Q7.6(D) Q7.7(D) Q7.8(D) Q7.9(D) R161.2 ; port L+7
L+8: C16.2 Q8.5(D) Q8.6(D) Q8.7(D) Q8.8(D) Q8.9(D) R162.2 ; port L+8
SCLK: U10.9(SCLK) U11.9(SCLK) ; port SCLK
NetC15_2: C15.2 R32.2 U10.6(ISNS)
NetC20_2: C20.2 R36.2 U11.6(ISNS)
NetQ1_1: Q1.1(S) Q1.2(S) Q1.3(S) R155.1 U10.38(OUT1) U10.39(OUT1)
NetQ1_4: Q1.4(G) U10.40(RCB1)
NetQ2_1: Q2.1(S) Q2.2(S) Q2.3(S) R156.1 U10.32(OUT2) U10.33(OUT2)
NetQ2_4: Q2.4(G) U10.31(RCB2)
NetQ3_1: Q3.1(S) Q3.2(S) Q3.3(S) R157.1 U10.12(OUT3) U10.13(OUT3)
NetQ3_4: Q3.4(G) U10.11(RCB3)
NetQ4_1: Q4.1(S) Q4.2(S) Q4.3(S) R158.1 U10.18(OUT4) U10.19(OUT4)
NetQ4_4: Q4.4(G) U10.20(RCB4)
NetQ5_1: Q5.1(S) Q5.2(S) Q5.3(S) R159.1 U11.38(OUT1) U11.39(OUT1)
NetQ5_4: Q5.4(G) U11.40(RCB1)
NetQ6_1: Q6.1(S) Q6.2(S) Q6.3(S) R160.1 U11.32(OUT2) U11.33(OUT2)
NetQ6_4: Q6.4(G) U11.31(RCB2)
NetQ7_1: Q7.1(S) Q7.2(S) Q7.3(S) R161.1 U11.12(OUT3) U11.13(OUT3)
NetQ7_4: Q7.4(G) U11.11(RCB3)
NetQ8_1: Q8.1(S) Q8.2(S) Q8.3(S) R162.1 U11.18(OUT4) U11.19(OUT4)
NetQ8_4: Q8.4(G) U11.20(RCB4)
NetR27_2: R27.2 U10.28(DSPI)
NetR28_1: R28.1 U10.3(DO_EN)
NetR30_1: R30.1 U10.29(REG_EN)
NetR31_2: R31.2 U10.30(ADDCFG)
NetR33_2: R33.2 U11.28(DSPI)
NetR34_1: R34.1 U11.3(DO_EN)
NetR37_1: R37.1 U11.29(REG_EN)
NetR38_2: R38.2 U11.30(ADDCFG)

Not connected (* = marked no-connect by the designer): U10 1(~{READY}) 22(LEDOUT1) 23(LEDOUT2) 24(LEDOUT3) 25(LEDOUT4) 26(NC) 27(NC); U11 1(~{READY}) 22(LEDOUT1) 23(LEDOUT2) 24(LEDOUT3) 25(LEDOUT4) 26(NC) 27(NC)

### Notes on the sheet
- (near U10) Address: 000
- (near Q8) Remove and short FETs if reverse current blocking is not needed
- (near U11) Address: 010

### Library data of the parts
C11-C14 C16-C19 = CMP-0119538-1: WCAP-CSGP Multilayer Ceramic Chip Capacitor, General Purpose, size 0805, X7R, 22nF, 100VDC; Manufacturer: Wurth Elektronik; Capacitance Tolerance: +/-10%; Case/Size Code: 0805; Dissipation Factor: 2.5%; Insulation Resistance: 4.5GOhm; Technical Reference: X7R0805223K100DFCT10000
C15 C20 = CMP-0097308-1: 100 pF ±5% 100V Ceramic Capacitor C0G, NP0 0402 (1005 Metric); Manufacturer: Wurth Electronics; Value: 100pF; SizeZ_mm: 0.55mm; TempCo: 30ppm/°C; AEC Qualified: No
C21 C22 C148 C163 = CMP-0119705-1: WCAP-CSGP Multilayer Ceramic Chip Capacitor, General Purpose, size 1210, X7R, 2.2µF, 100VDC; Manufacturer: Wurth Elektronik; PartNumber: '885012209071; Capacitance Tolerance: +/-10%; Case/Size Code: 1210; Dissipation Factor: 5%; Insulation Resistance: 0.05GOhm; Technical Reference: X7R1210225K100DFCT10000
C23 C24 = CMP-0119143-1: as C3-C10 on sheet RemoteIO_IO
Q1-Q8 = CMP-0000826-2: MOSFET, N-CH, 60 V, 35 A, DNH0008A (VSONP-8); Alternate Manufacturer: None; Manufacturer: Texas Instruments; SizeZ_mm: 0.9; ChType: N; Value2: 11.1 nC; Value1: 0.01; VdsMax_V: 60V; SizeX_mm: 3.3; SizeAreaWB_mm2: 18.49; Vgs_V: 20V; QgTyp_nC: 11.1; Value: 60V; Rdson45_ohm: 12m; SizeArea_mm2: 10.89; AEC Category: Q101; IdsMax_A: 35A; ChMode: Enhancement
R27 R28 R30 R33 R34 R37 R155-R162 = CMP-0093210-1: as R1 on sheet RemoteIO_IOLinkPort
R29 = CMP-0026825-5: as R2 on sheet RemoteIO_IOLinkPort
R31 = CMP-0026004-3: RES, 13.3 k, 1%, 0.063 W, AEC-Q200 Grade 0, 0402; Manufacturer: Vishay-Dale; Power_W: 63mW; TempCo: 100 ppm/C; Value_Code: 13k3; Value: 13.3k; EIA_Code: E96; SizeX_mm: 1; SizeY_mm: 0.5; SizeZ_mm: 0.6; Value2: 0.063W; AEC Qualified: Y; VDC_V: 50V; AEC Category: Q200; AEC Grade: 0
R32 R36 = CMP-0026071-3: as R3-R18 on sheet RemoteIO_IO
R38 = CMP-0026187-2: RES, 23.7 k, 1%, 0.063 W, AEC-Q200 Grade 0, 0402; Manufacturer: Vishay-Dale; Power_W: 63mW; TempCo: 100 ppm/C; Value_Code: 23k7; Value: 23.7k; EIA_Code: E96; SizeX_mm: 1; SizeY_mm: 0.5; SizeZ_mm: 0.6; Value2: 0.063W; AEC Qualified: Y; VDC_V: 50V; AEC Category: Q200; AEC Grade: 0
U10 U11 = CMP-0093389-2: 65-mΩ, Quad-Channel Smart High-Side Switch with SPI interface and Diagnostics; Manufacturer: Texas Instruments; AEC Category: Q200; Max Supply Voltage: 36V; Turn On Delay Time: 30us; CompType: IC; AEC Qualified: No; Min Supply Voltage: 3V; Number Of Drivers: 4; TaMin_C: -40°C; TJmax_C: +150°C; Standoff Height: 0mm; TaMax_C: +125°C; SizeZ_mm: 1mm

## Sheet RemoteIO_Flash.SchDoc
size 431 x 279 mm; Date: Not shown in title block; ApprovedBy: Not shown in title block; CheckedBy: Not shown in title block; Author: Not shown in title block; CompanyName: Not shown in title block; Engineer: Not shown in title block; Organization: Not shown in title block; Address1: Not shown in title block; Address2: Not shown in title block; Address3: Not shown in title block; Address4: Not shown in title block; DocumentNumber: 6; Revision: Use project parameter SCH_Rev; SheetNumber: 6; SheetTotal: 14; PageSetup: Record=PageOptions¦CenterHorizontal=True¦CenterVertical=True¦PrintScale=1.00¦XCorrection=1.00¦YCorrection=1.00¦PrintKind=0¦BorderSize=5000000¦LeftOffset=0¦BottomOffset=0¦Orientation=2¦PaperLength=1000¦PaperWidth=1000¦Scale=100¦PaperSource=15¦PrintQuality=600¦MediaType=1¦DitherType=10¦PaperKind=Letter¦PrintScaleMode=1
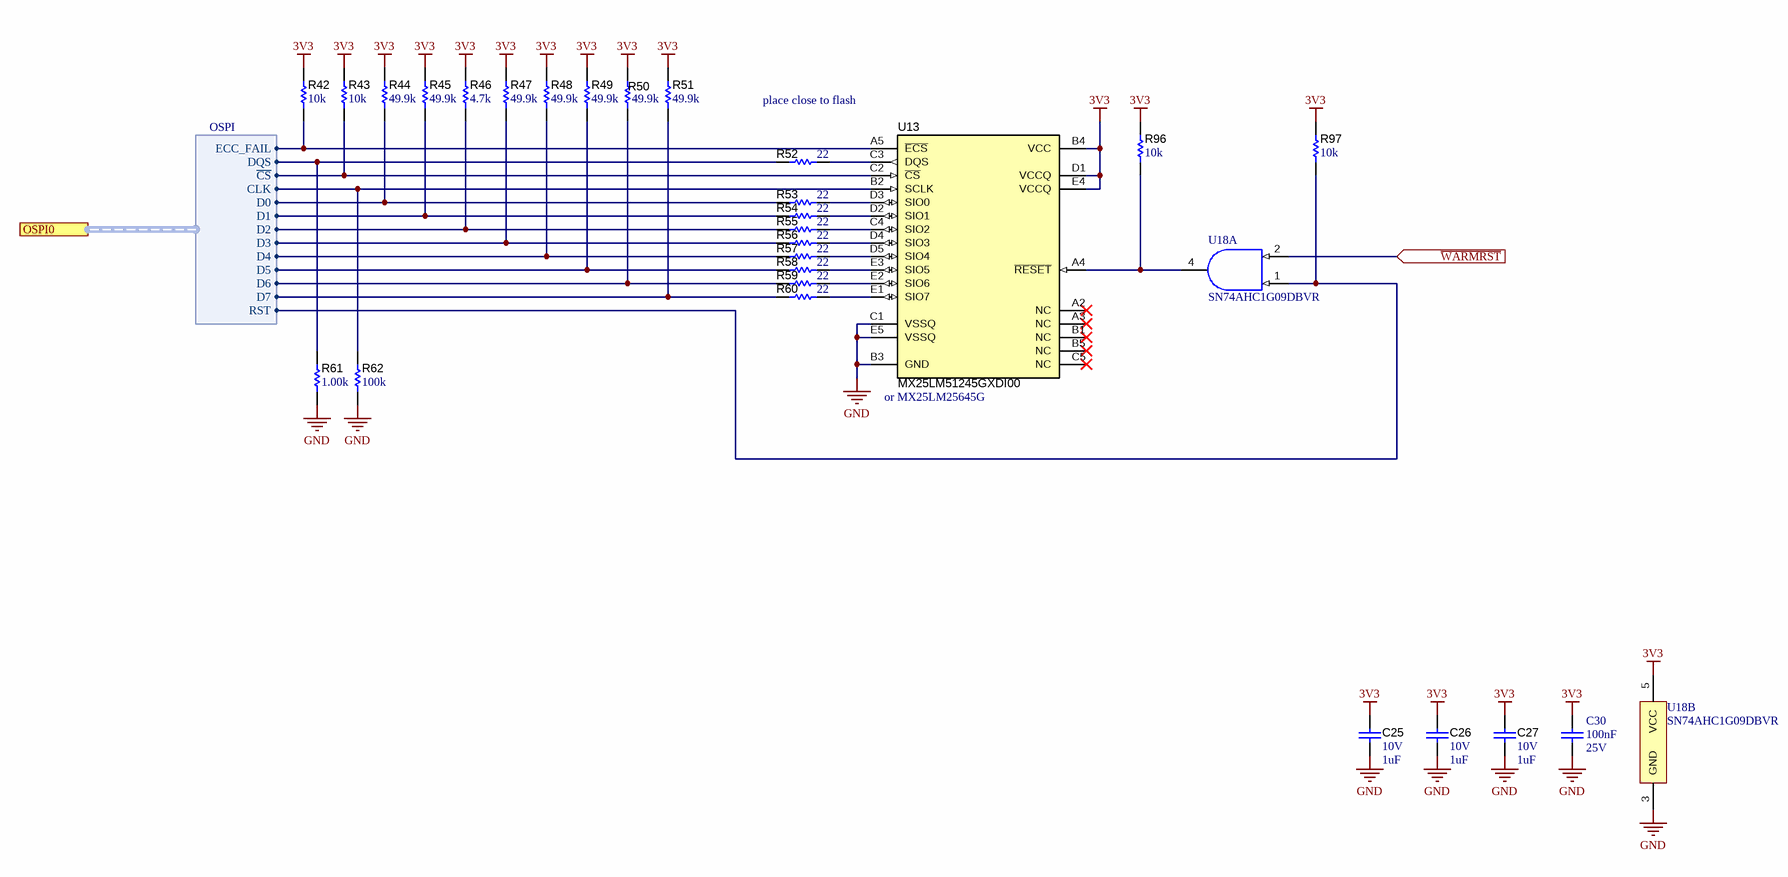
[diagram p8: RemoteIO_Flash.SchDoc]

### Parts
C25  VDC_V: 10V  ValueDisplayed: 1uF  [0402]  (hidden comment: 885012105012)
C26  VDC_V: 10V  ValueDisplayed: 1uF  [0402]  (hidden comment: 885012105012)
C27  VDC_V: 10V  ValueDisplayed: 1uF  [0402S]  (hidden comment: 885012105012)
C30  Cap_F: 100nF  Rated Voltage (DC): 25V  [WCAP-CSGP_0402_L1W0.5H0.5]  (hidden comment: 885012105018)
R42  ValueDisplayed: 10k  [0402S]  (hidden comment: CRCW040210K0JNED)
R43  ValueDisplayed: 10k  [0402S]  (hidden comment: CRCW040210K0JNED)
R44  ValueDisplayed: 49.9k  [0201L]  (hidden comment: RC0201FR-7D49K9L)
R45  ValueDisplayed: 49.9k  [0201L]  (hidden comment: RC0201FR-7D49K9L)
R46  ValueDisplayed: 4.7k  [0201L]  (hidden comment: RC0201JR-7D4K7L)
R47  ValueDisplayed: 49.9k  [0201L]  (hidden comment: RC0201FR-7D49K9L)
R48  ValueDisplayed: 49.9k  [0201L]  (hidden comment: RC0201FR-7D49K9L)
R49  ValueDisplayed: 49.9k  [0201L]  (hidden comment: RC0201FR-7D49K9L)
R50  ValueDisplayed: 49.9k  [0201L]  (hidden comment: RC0201FR-7D49K9L)
R51  ValueDisplayed: 49.9k  [0201L]  (hidden comment: RC0201FR-7D49K9L)
R52  ValueDisplayed: 22  [0201L]  (hidden comment: RC0201JR-7D22RL)
R53  ValueDisplayed: 22  [0201L]  (hidden comment: RC0201JR-7D22RL)
R54  ValueDisplayed: 22  [0201L]  (hidden comment: RC0201JR-7D22RL)
R55  ValueDisplayed: 22  [0201L]  (hidden comment: RC0201JR-7D22RL)
R56  ValueDisplayed: 22  [0201L]  (hidden comment: RC0201JR-7D22RL)
R57  ValueDisplayed: 22  [0201L]  (hidden comment: RC0201JR-7D22RL)
R58  ValueDisplayed: 22  [0201L]  (hidden comment: RC0201JR-7D22RL)
R59  ValueDisplayed: 22  [0201L]  (hidden comment: RC0201JR-7D22RL)
R60  ValueDisplayed: 22  [0201L]  (hidden comment: RC0201JR-7D22RL)
R61  ValueDisplayed: 1.00k  [0402S]  (hidden comment: CRCW04021K00FKED)
R62  ValueDisplayed: 100k  [0402S]  (hidden comment: RC0402FR-07100KL)
R96  ValueDisplayed: 10k  [0402S]  (hidden comment: CRCW040210K0JNED)
R97  ValueDisplayed: 10k  [0402]  (hidden comment: CRCW040210K0JNED)
U13  MX25LM51245GXDI00  [MXIC_BGA24-6x8MM]
U18  SN74AHC1G09DBVR  [DBV0005A_N]  (parts A,B of 2)

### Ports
OSPI0 (harness OSPI), ~{WARMRST} (in)

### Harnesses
OSPI: ~{CS}, CLK, D0, D1, D2, D3, D4, D5, D6, D7, DQS, ECC_FAIL, RST

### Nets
3V3: C25.1 C26.1 C27.1 C30.2 R42.2 R43.2 R44.2 R45.2 R46.2 R47.2 R48.2 R49.2 R50.2 R51.2 R96.2 R97.2 U13.B4(VCC) U13.D1(VCCQ) U13.E4(VCCQ) U18.5(VCC)
GND: C25.2 C26.2 C27.2 C30.1 R61.1 R62.1 U13.B3(GND) U13.C1(VSSQ) U13.E5(VSSQ) U18.3(GND)
~{WARMRST}: U18.2(B) ; port ~{WARMRST}
OSPI0_~{CS}: R43.1 U13.C2(~{CS}) ; port OSPI0.~{CS}
OSPI0_CLK: R62.2 U13.B2(SCLK) ; port OSPI0.CLK
OSPI0_D0: R44.1 R53.1 ; port OSPI0.D0
OSPI0_D1: R45.1 R54.1 ; port OSPI0.D1
OSPI0_D2: R46.1 R55.1 ; port OSPI0.D2
OSPI0_D3: R47.1 R56.1 ; port OSPI0.D3
OSPI0_D4: R48.1 R57.1 ; port OSPI0.D4
OSPI0_D5: R49.1 R58.1 ; port OSPI0.D5
OSPI0_D6: R50.1 R59.1 ; port OSPI0.D6
OSPI0_D7: R51.1 R60.1 ; port OSPI0.D7
OSPI0_DQS: R52.1 R61.2 ; port OSPI0.DQS
OSPI0_ECC_FAIL: R42.1 U13.A5(~{ECS}) ; port OSPI0.ECC_FAIL
OSPI0_RST: R97.1 U18.1(A) ; port OSPI0.RST
NetR52_2: R52.2 U13.C3(DQS)
NetR53_2: R53.2 U13.D3(SIO0)
NetR54_2: R54.2 U13.D2(SIO1)
NetR55_2: R55.2 U13.C4(SIO2)
NetR56_2: R56.2 U13.D4(SIO3)
NetR57_2: R57.2 U13.D5(SIO4)
NetR58_2: R58.2 U13.E3(SIO5)
NetR59_2: R59.2 U13.E2(SIO6)
NetR60_2: R60.2 U13.E1(SIO7)
NetR96_1: R96.1 U13.A4(~{RESET}) U18.4(Y)

Not connected (* = marked no-connect by the designer): U13 A2(NC)* A3(NC)* B1(NC)* B5(NC)* C5(NC)*

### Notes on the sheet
- place close to flash
- (near U13) or MX25LM25645G

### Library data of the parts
C25 C26 = CMP-0064924-2: CAP, CERM, 1 uF, 10 V,+/- 20%, X5R, 0402; Manufacturer: Wurth Elektronik; TaMin_C: -55°C; Polarized: N; SizeAreaWB_mm2: 3; Value1: Unknown; U/M: EA; Value: 1uF; TaMax_C: 85°C; SizeZ_mm: 0.6; SizeX_mm: 1; SizeY_mm: 0.5; Cap_F: 1µF; AEC Category: Q200
C27 = CMP-0064924-2: CAP, CERM, 1 uF, 10 V,+/- 20%, X5R, 0402; Manufacturer: Wurth Elektronik; TaMin_C: -55°C; Polarized: N; SizeAreaWB_mm2: 3; Value1: Unknown; U/M: EA; Value: 1uF; TaMax_C: 85°C; SizeZ_mm: 0.6; SizeX_mm: 1; SizeY_mm: 0.5; Cap_Case: 0402; Cap_F: 1µF; AEC Category: Q200
C30 = CMP-0119143-1: as C3-C10 on sheet RemoteIO_IO
R42 R43 R96 R97 = CMP-0026825-5: as R2 on sheet RemoteIO_IOLinkPort
R44 R45 R47-R51 = CMP-0028027-1: RES, 49.9 k, 1%, 0.05 W, 0201; Manufacturer: Yageo America; Power_W: 50mW; TempCo: 200 ppm/C; Value_Code: 49k9; U/M: EA; Value: 49.9k; EIA_Code: E96; SizeX_mm: 0.6; SizeY_mm: 0.3; SizeZ_mm: 0.26; Value2: 0.05W; SizeArea_mm2: 0.18; AEC Qualified: N; VDC_V: 25V; AEC Category: Q200
R46 = CMP-0027242-1: RES, 4.7 k, 5%, 0.05 W, 0201; Manufacturer: Yageo America; Power_W: 50mW; TempCo: 200 ppm/C; Value_Code: 4k70; U/M: EA; Value: 4.7k; EIA_Code: E24; SizeX_mm: 0.6; SizeY_mm: 0.3; SizeZ_mm: 0.26; Value2: 0.05W; SizeArea_mm2: 0.18; AEC Qualified: N; VDC_V: 25V; AEC Category: Q200
R52-R60 = CMP-0027210-3: RES, 22, 5%, 0.05 W, 0201; Manufacturer: Yageo America; Power_W: 50mW; TempCo: 200 ppm/C; Value_Code: 22R0; U/M: EA; Value: 22; EIA_Code: E24; SizeX_mm: 0.6; SizeY_mm: 0.3; SizeZ_mm: 0.26; Value2: 0.05W; SizeArea_mm2: 0.18; AEC Qualified: N; VDC_V: 25V; AEC Category: Q200
R61 = CMP-0026071-3: as R3-R18 on sheet RemoteIO_IO
R62 = CMP-0026721-1: RES, 100 k, 1%, 0.0625 W, 0402; Manufacturer: Yageo America; Power_W: 62.5mW; TempCo: 100 ppm/C; U/M: EA; Value: 100k; EIA_Code: E96; SizeX_mm: 1; SizeY_mm: 0.5; SizeZ_mm: 0.6; AEC Qualified: N; VDC_V: 50V; AEC Category: Q200
U13 = CMP-0086110-1: 3V 512M-BIT [x 1/x 8] CMOS MXSMIO(R)(SERIAL MULTI I/O)FLASH MEMORY, BGA-24; Manufacturer: Macronix International Co., LTD; SizeX_mm: 6; SizeArea_mm2: 48; SizeZ_mm: 1.2; SizeAreaWB_mm2: 80; SizeY_mm: 8
U18 = CMP-0051264-2: Single 2-Input Positive–AND Gate with Open Drain Output,  DBV0005A (SOT-23-5); Manufacturer: Texas Instruments; 3-State Output: No; Input Type: CMOS; Bits(#): 1; F @ Nom Voltage(Max)(Mhz): 75; tpd @ Nom Voltage(Max)(ns): 11,7.5; Voltage(Nom)(V): 3.3,5; Output Drive (IOL/IOH)(Max)(mA): 50/-50; Gate Type: AND; VCC(Max)(V): 5.5; ICC @ Nom Voltage(Max)(mA): 0.01; VCC(Min)(V): 2; Logic: True; Rating: Catalog; AEC Category: Q200; AEC Qualified: N; CompType: IC; SizeAreaWB_mm2: 14.82; SizeArea_mm2: 8.12; SizeX_mm: 2.8; SizeY_mm: 2.9; SizeZ_mm: 1.45

## Sheet RemoteIO_RAM.SchDoc
size 431 x 279 mm; Date: Not shown in title block; ApprovedBy: Not shown in title block; CheckedBy: Not shown in title block; Author: Not shown in title block; CompanyName: Not shown in title block; Engineer: Not shown in title block; Organization: Not shown in title block; Address1: Not shown in title block; Address2: Not shown in title block; Address3: Not shown in title block; Address4: Not shown in title block; DocumentNumber: 7; Revision: Use project parameter SCH_Rev; SheetNumber: 7; SheetTotal: 14; PageSetup: Record=PageOptions¦CenterHorizontal=True¦CenterVertical=True¦PrintScale=1.00¦XCorrection=1.00¦YCorrection=1.00¦PrintKind=0¦BorderSize=5000000¦LeftOffset=0¦BottomOffset=0¦Orientation=2¦PaperLength=1000¦PaperWidth=1000¦Scale=100¦PaperSource=15¦PrintQuality=600¦MediaType=1¦DitherType=10¦PaperKind=Letter¦PrintScaleMode=1
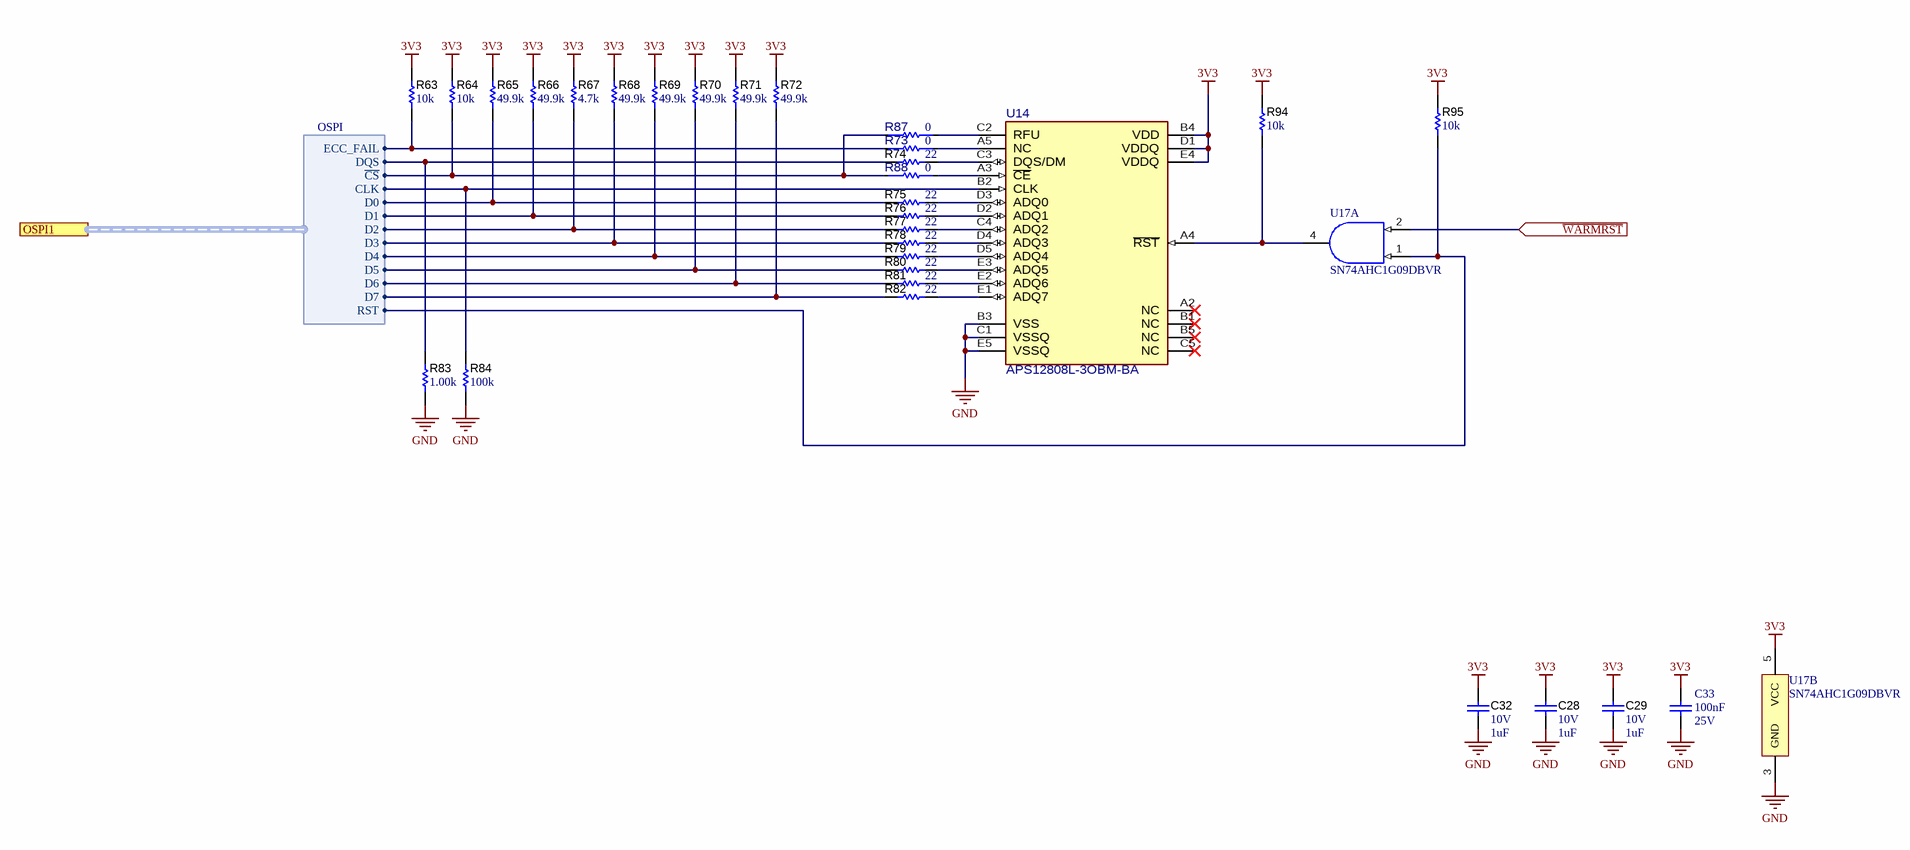
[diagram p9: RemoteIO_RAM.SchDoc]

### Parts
C28  VDC_V: 10V  ValueDisplayed: 1uF  [0402]  (hidden comment: 885012105012)
C29  VDC_V: 10V  ValueDisplayed: 1uF  [0402]  (hidden comment: 885012105012)
C32  VDC_V: 10V  ValueDisplayed: 1uF  [0402]  (hidden comment: 885012105012)
C33  Cap_F: 100nF  Rated Voltage (DC): 25V  [WCAP-CSGP_0402_L1W0.5H0.5]  (hidden comment: 885012105018)
R63  ValueDisplayed: 10k  [0402S]  (hidden comment: CRCW040210K0JNED)
R64  ValueDisplayed: 10k  [0402S]  (hidden comment: CRCW040210K0JNED)
R65  ValueDisplayed: 49.9k  [0201L]  (hidden comment: RC0201FR-7D49K9L)
R66  ValueDisplayed: 49.9k  [0201L]  (hidden comment: RC0201FR-7D49K9L)
R67  ValueDisplayed: 4.7k  [0201L]  (hidden comment: RC0201JR-7D4K7L)
R68  ValueDisplayed: 49.9k  [0201L]  (hidden comment: RC0201FR-7D49K9L)
R69  ValueDisplayed: 49.9k  [0201L]  (hidden comment: RC0201FR-7D49K9L)
R70  ValueDisplayed: 49.9k  [0201L]  (hidden comment: RC0201FR-7D49K9L)
R71  ValueDisplayed: 49.9k  [0201L]  (hidden comment: RC0201FR-7D49K9L)
R72  ValueDisplayed: 49.9k  [0201L]  (hidden comment: RC0201FR-7D49K9L)
R73  value 0  [FP-CRCW04020000Z0EDC_0402-MFG]  (hidden comment: CRCW04020000Z0EDC)
R74  ValueDisplayed: 22  [0201L]  (hidden comment: RC0201JR-7D22RL)
R75  ValueDisplayed: 22  [0201L]  (hidden comment: RC0201JR-7D22RL)
R76  ValueDisplayed: 22  [0201L]  (hidden comment: RC0201JR-7D22RL)
R77  ValueDisplayed: 22  [0201L]  (hidden comment: RC0201JR-7D22RL)
R78  ValueDisplayed: 22  [0201L]  (hidden comment: RC0201JR-7D22RL)
R79  ValueDisplayed: 22  [0201L]  (hidden comment: RC0201JR-7D22RL)
R80  ValueDisplayed: 22  [0201L]  (hidden comment: RC0201JR-7D22RL)
R81  ValueDisplayed: 22  [0201L]  (hidden comment: RC0201JR-7D22RL)
R82  ValueDisplayed: 22  [0201L]  (hidden comment: RC0201JR-7D22RL)
R83  ValueDisplayed: 1.00k  [0402S]  (hidden comment: CRCW04021K00FKED)
R84  ValueDisplayed: 100k  [0402S]  (hidden comment: RC0402FR-07100KL)
R87  value 0  [FP-CRCW04020000Z0EDC_0402-MFG]  (hidden comment: CRCW04020000Z0EDC)
R88  value 0  [FP-CRCW04020000Z0EDC_0402-MFG]  (hidden comment: CRCW04020000Z0EDC)
R94  ValueDisplayed: 10k  [0402]  (hidden comment: CRCW040210K0JNED)
R95  ValueDisplayed: 10k  [0402]  (hidden comment: CRCW040210K0JNED)
U14  APS12808L-3OBM-BA  [FP-APS12808L-3OBM-BA_BGA24-IPC_C]
U17  SN74AHC1G09DBVR  [DBV0005A_N]  (parts A,B of 2)

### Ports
OSPI1 (harness OSPI), ~{WARMRST} (in)

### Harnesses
OSPI: ~{CS}, CLK, D0, D1, D2, D3, D4, D5, D6, D7, DQS, ECC_FAIL, RST

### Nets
3V3: C28.1 C29.1 C32.1 C33.2 R63.2 R64.2 R65.2 R66.2 R67.2 R68.2 R69.2 R70.2 R71.2 R72.2 R94.2 R95.2 U14.B4(VDD) U14.D1(VDDQ) U14.E4(VDDQ) U17.5(VCC)
GND: C28.2 C29.2 C32.2 C33.1 R83.1 R84.1 U14.B3(VSS) U14.C1(VSSQ) U14.E5(VSSQ) U17.3(GND)
~{WARMRST}: U17.2(B) ; port ~{WARMRST}
OSPI1_~{CS}: R64.1 R87.1 R88.1 ; port OSPI1.~{CS}
OSPI1_CLK: R84.2 U14.B2(CLK) ; port OSPI1.CLK
OSPI1_D0: R65.1 R75.1 ; port OSPI1.D0
OSPI1_D1: R66.1 R76.1 ; port OSPI1.D1
OSPI1_D2: R67.1 R77.1 ; port OSPI1.D2
OSPI1_D3: R68.1 R78.1 ; port OSPI1.D3
OSPI1_D4: R69.1 R79.1 ; port OSPI1.D4
OSPI1_D5: R70.1 R80.1 ; port OSPI1.D5
OSPI1_D6: R71.1 R81.1 ; port OSPI1.D6
OSPI1_D7: R72.1 R82.1 ; port OSPI1.D7
OSPI1_DQS: R74.1 R83.2 ; port OSPI1.DQS
OSPI1_ECC_FAIL: R63.1 R73.1 ; port OSPI1.ECC_FAIL
OSPI1_RST: R95.1 U17.1(A) ; port OSPI1.RST
NetR73_2: R73.2 U14.A5(NC)
NetR74_2: R74.2 U14.C3(DQS/DM)
NetR75_2: R75.2 U14.D3(ADQ0)
NetR76_2: R76.2 U14.D2(ADQ1)
NetR77_2: R77.2 U14.C4(ADQ2)
NetR78_2: R78.2 U14.D4(ADQ3)
NetR79_2: R79.2 U14.D5(ADQ4)
NetR80_2: R80.2 U14.E3(ADQ5)
NetR81_2: R81.2 U14.E2(ADQ6)
NetR82_2: R82.2 U14.E1(ADQ7)
NetR87_2: R87.2 U14.C2(RFU)
NetR88_2: R88.2 U14.A3(~{CE})
NetR94_1: R94.1 U14.A4(~{RST}) U17.4(Y)

Not connected (* = marked no-connect by the designer): U14 A2(NC)* B1(NC)* B5(NC)* C5(NC)*

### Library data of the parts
C28 C29 C32 = CMP-0064924-2: as C25 on sheet RemoteIO_Flash
C33 = CMP-0119143-1: as C3-C10 on sheet RemoteIO_IO
R63 R64 R94 R95 = CMP-0026825-5: as R2 on sheet RemoteIO_IOLinkPort
R65 R66 R68-R72 = CMP-0028027-1: as R44 on sheet RemoteIO_Flash
R67 = CMP-0027242-1: as R46 on sheet RemoteIO_Flash
R73 R87 R88 = CMP-0093210-1: as R1 on sheet RemoteIO_IOLinkPort
R74-R82 = CMP-0027210-3: as R52 on sheet RemoteIO_Flash
R83 = CMP-0026071-3: as R3-R18 on sheet RemoteIO_IO
R84 = CMP-0026721-1: as R62 on sheet RemoteIO_Flash
U14 = CMP-0126808-1: DRAM IoT RAM 128Mb OPI (x8) DDR 133MHz, 3V, Ind. Temp., BGA24; Manufacturer: AP Memory; SizeZ_mm: 1.2mm; Access Time: 5.5ns; AEC Qualified: No; Interface: SPI; Max Supply Voltage: 3.6V; Memory Size: 128Mbits; Min Supply Voltage: 2.7V; Nominal Supply Current: 500-700uA; Standoff Height: 0.25mm
U17 = CMP-0051264-2: as U18 on sheet RemoteIO_Flash

## Sheet RemoteIO_SOP.SchDoc
size 431 x 279 mm; Date: Not shown in title block; ApprovedBy: Not shown in title block; CheckedBy: Not shown in title block; Author: Not shown in title block; CompanyName: Not shown in title block; Engineer: Not shown in title block; Organization: Not shown in title block; Address1: Not shown in title block; Address2: Not shown in title block; Address3: Not shown in title block; Address4: Not shown in title block; DocumentNumber: 8; Revision: Use project parameter SCH_Rev; SheetNumber: 8; SheetTotal: 14; PageSetup: Record=PageOptions¦CenterHorizontal=True¦CenterVertical=True¦PrintScale=1.00¦XCorrection=1.00¦YCorrection=1.00¦PrintKind=0¦BorderSize=5000000¦LeftOffset=0¦BottomOffset=0¦Orientation=2¦PaperLength=1000¦PaperWidth=1000¦Scale=100¦PaperSource=15¦PrintQuality=600¦MediaType=1¦DitherType=10¦PaperKind=Letter¦PrintScaleMode=1
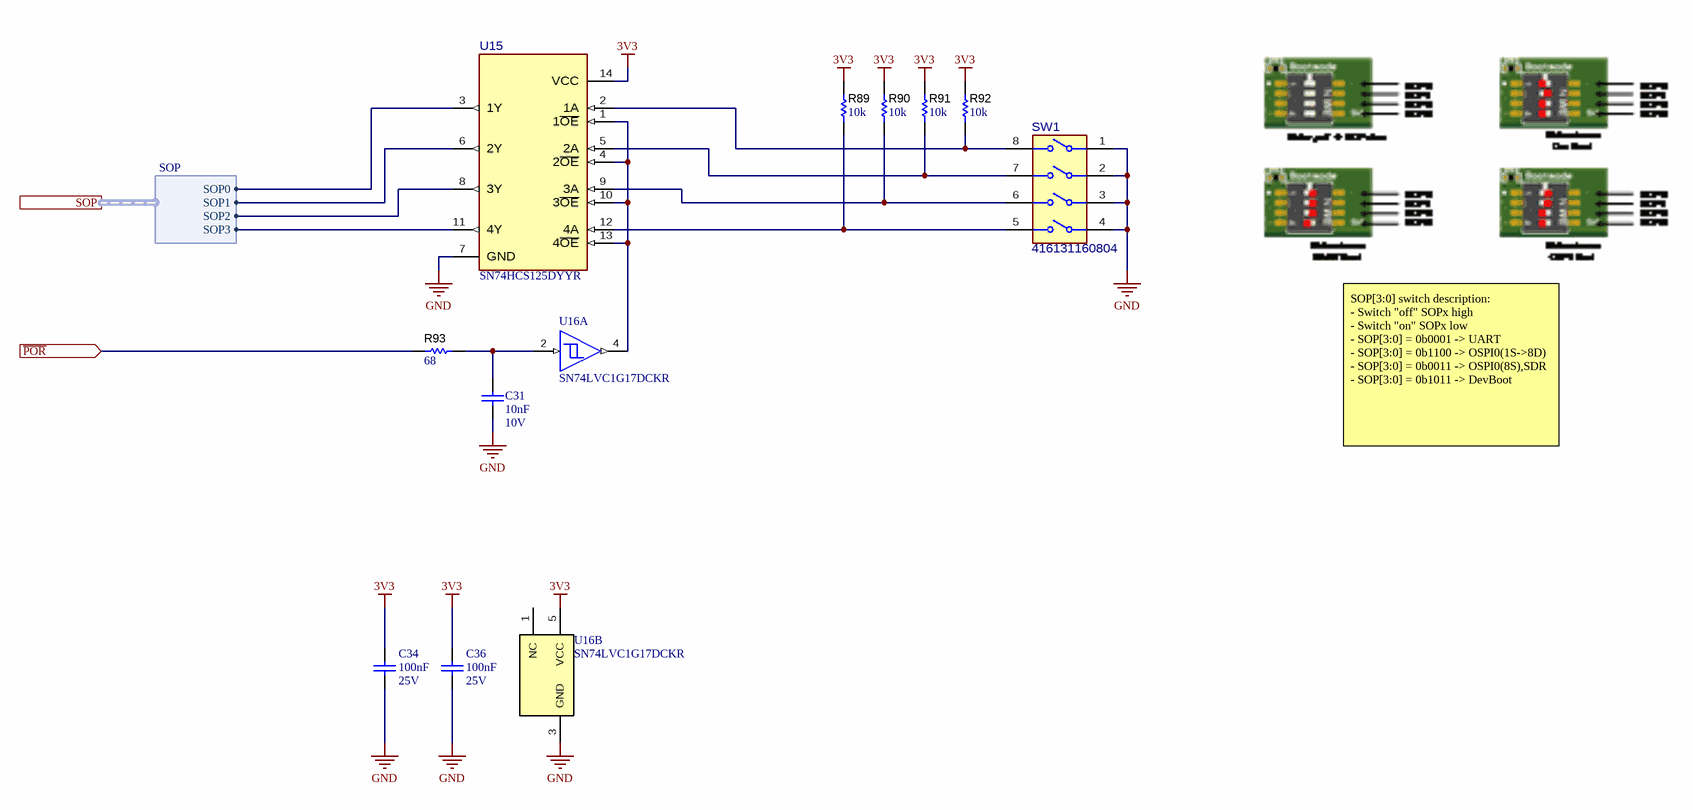
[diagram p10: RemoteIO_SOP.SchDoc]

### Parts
C31  Cap_F: 10nF  Rated Voltage (DC): 10V  [WCAP-CSGP_0402_L1W0.5H0.5]  (hidden comment: 885012205012)
C34  Cap_F: 100nF  Rated Voltage (DC): 25V  [WCAP-CSGP_0402_L1W0.5H0.5]  (hidden comment: 885012105018)
C36  Cap_F: 100nF  Rated Voltage (DC): 25V  [WCAP-CSGP_0402_L1W0.5H0.5]  (hidden comment: 885012105018)
R89  ValueDisplayed: 10k  [0402]  (hidden comment: CRCW040210K0JNED)
R90  ValueDisplayed: 10k  [0402]  (hidden comment: CRCW040210K0JNED)
R91  ValueDisplayed: 10k  [0402]  (hidden comment: CRCW040210K0JNED)
R92  ValueDisplayed: 10k  [0402]  (hidden comment: CRCW040210K0JNED)
R93  ValueDisplayed: 68  [0402]  (hidden comment: CRCW040268R0JNED)
SW1  416131160804  [FP-416131160804_SMT_SW-MFG]
U15  SN74HCS125DYYR  [DYY0014A-MFG]
U16  SN74LVC1G17DCKR  [DCK0005A_N]  (parts A,B of 2)

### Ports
SOP (harness SOP), ~{POR} (in)

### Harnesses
SOP: SOP0, SOP1, SOP2, SOP3

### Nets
3V3: C34.2 C36.2 R89.2 R90.2 R91.2 R92.2 U15.14(VCC) U16.5(VCC)
GND: C31.1 C34.1 C36.1 SW1.1 SW1.2 SW1.3 SW1.4 U15.7(GND) U16.3(GND)
~{POR}: R93.1 ; port ~{POR}
IO_EN2: U15.8(3Y) ; port SOP.SOP2
IO_TX7: U15.6(2Y) ; port SOP.SOP1
IO_TX8: U15.3(1Y) ; port SOP.SOP0
LED_ERR: U15.11(4Y) ; port SOP.SOP3
NetC31_2: C31.2 R93.2 U16.2(A)
NetR89_1: R89.1 SW1.5 U15.12(4A)
NetR90_1: R90.1 SW1.6 U15.9(3A)
NetR91_1: R91.1 SW1.7 U15.5(2A)
NetR92_1: R92.1 SW1.8 U15.2(1A)
NetU15_1: U15.1(1~{OE}) U15.4(2~{OE}) U15.10(3~{OE}) U15.13(4~{OE}) U16.4(Y)

Not connected (* = marked no-connect by the designer): U16 1(NC)

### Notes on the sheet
- SOP[3:0] switch description:
  - Switch "off" SOPx high
  - Switch "on" SOPx low
  - SOP[3:0] = 0b0001 -> UART                       - SOP[3:0] = 0b1100 -> OSPI0(1S->8D)                                  - SOP[3:0] = 0b0011 -> OSPI0(8S),SDR                       - SOP[3:0] = 0b1011 -> DevBoot

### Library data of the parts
C31 = CMP-0119242-1: WCAP-CSGP Multilayer Ceramic Chip Capacitor, General Purpose, size 0402, X7R, 10nF, 10VDC; Manufacturer: Wurth Elektronik; Capacitance Tolerance: +/-10%; Case/Size Code: 0402; Dissipation Factor: 5%; Insulation Resistance: 10GOhm; Technical Reference: X7R0402103K010DFCT10000
C34 C36 = CMP-0119143-1: as C3-C10 on sheet RemoteIO_IO
R89-R92 = CMP-0026825-5: as R2 on sheet RemoteIO_IOLinkPort
R93 = CMP-0026964-3: RES, 68, 5%, 0.063 W, AEC-Q200 Grade 0, 0402; Manufacturer: Vishay-Dale; Power_W: 63mW; TempCo: 200 ppm/C; Value_Code: 68R0; Value: 68; EIA_Code: E24; SizeX_mm: 1; SizeY_mm: 0.5; SizeZ_mm: 0.6; Value2: 0.063W; AEC Qualified: Y; VDC_V: 50V; AEC Category: Q200; AEC Grade: 0
SW1 = CMP-0093176-1: Dip Switch SPST 4 Position Surface Mount Slide (Standard) Actuator 25mA 24VDC; Manufacturer: Wurth; PositionCount: 4; Electromechanical Life: 1000Cycles; Circuit: 4PST; Coil Resistance_ohm: 100mΩ; VDC_V: 24V; Standoff Height: 0mm; SizeZ_mm: 2.65mm; AEC Qualified: No
U15 = CMP-0127143-1: Schmitt-trigger inputs quadruple bus buffer gates with 3-state outputs 14-SOT-23-THIN -40 to 125; Manufacturer: Texas Instruments; SizeZ_mm: 1.1mm; AEC Qualified: No; Logic Function Desc: Non-Inverting; Max Supply Voltage: 6V; Min Supply Voltage: 2V; Nominal Supply Current: 0.1uA; Number Of Inputs: 4; PositionCount: 1; Propagation Delay: 5ns; Standoff Height: 0mm; TaMax_C: +125°C; TaMin_C: -40°C; TJmax_C: +150°C
U16 = CMP-0051704-3: Single Schmitt-Trigger Buffer, DCK0005A, LARGE T&R; Manufacturer: Texas Instruments; tpd @ Nom Voltage(Max)(ns): 11,6.5,5.5,5; Bits(#): 1; VCC(Min)(V): 1.65; F @ Nom Voltage(Max)(Mhz): 150; VCC(Max)(V): 5.5; Input Type: CMOS/TTL; Sub-Family: Non-Inverting Buffer/Driver; Output Type: CMOS; Output Drive (IOL/IOH)(Max)(mA): 32/-32; 3-State Output: No; Logic: True; ICC @ Nom Voltage(Max)(mA): 0.01; Voltage(Nom)(V): 1.8,2.5,3.3,5; Rating: Catalog; Schmitt Trigger: Yes; Technology Family: LVC; AEC Category: Q200; AEC Qualified: N; CompType: IC; SizeAreaWB_mm2: 9.3; SizeArea_mm2: 4.2; SizeX_mm: 2.1; SizeY_mm: 2.0; SizeZ_mm: 1.1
